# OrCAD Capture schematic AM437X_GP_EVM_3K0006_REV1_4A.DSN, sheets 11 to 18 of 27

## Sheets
11 Pg24: Keypad/LED's: size C
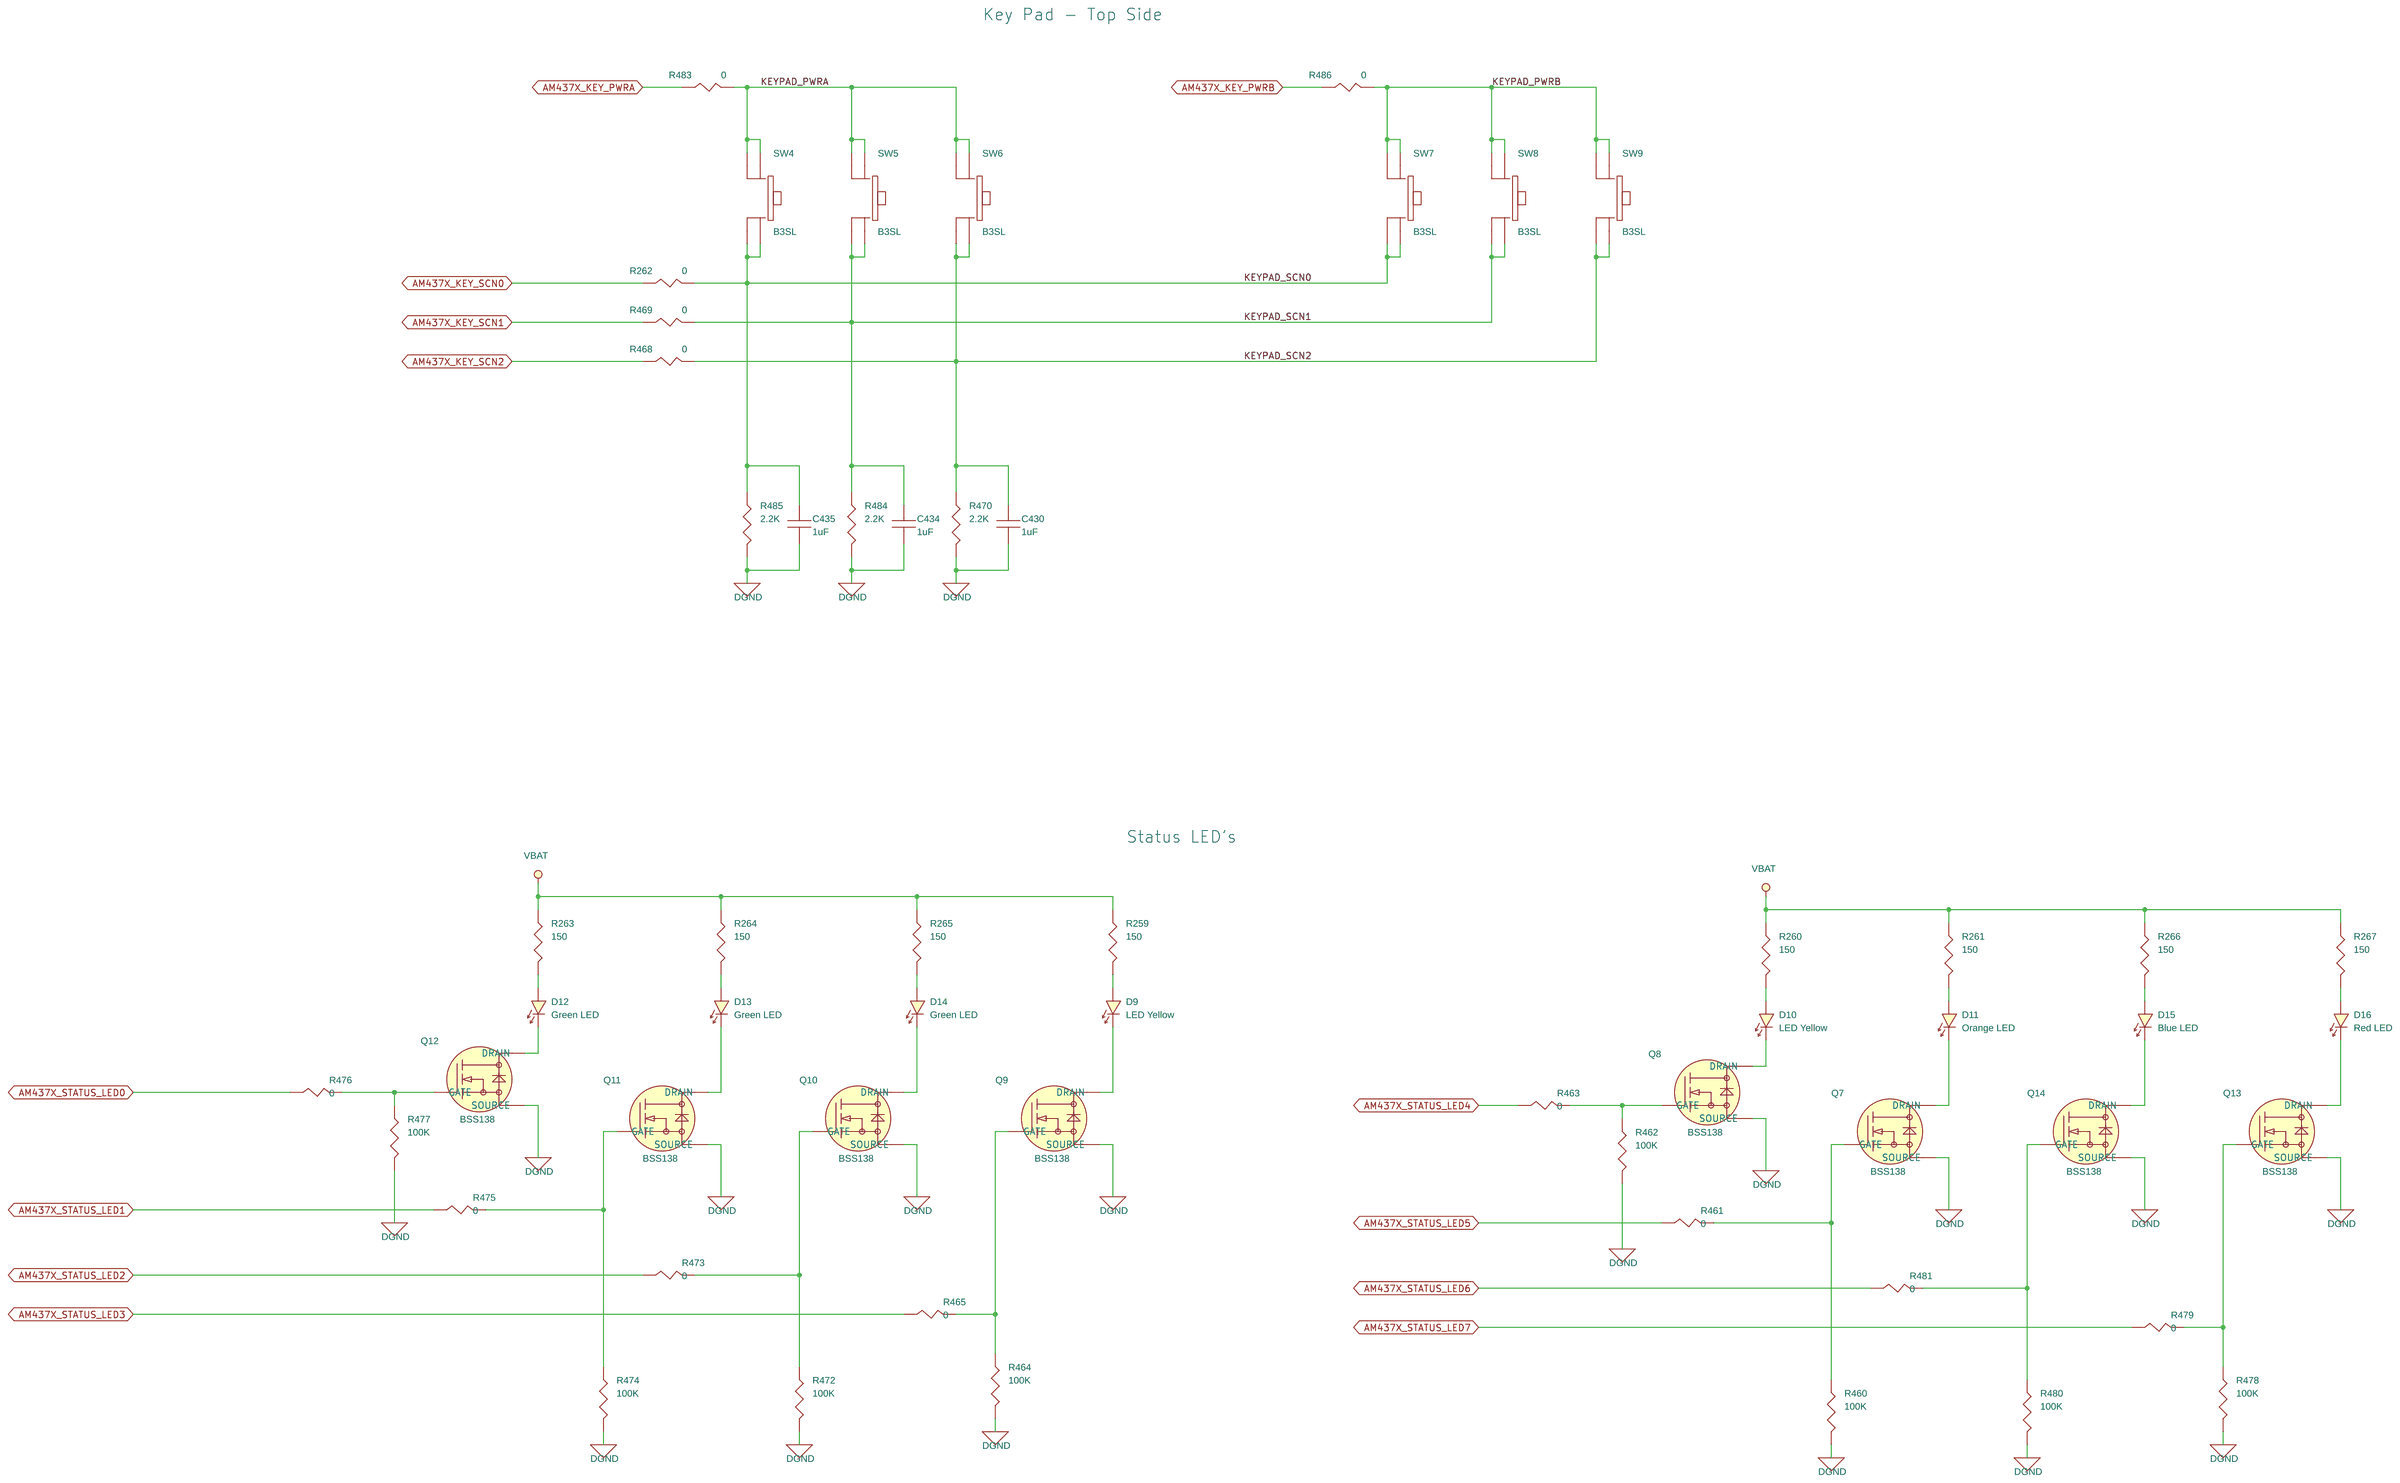
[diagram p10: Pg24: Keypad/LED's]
12 Pg06: DDR3 Memory: size C
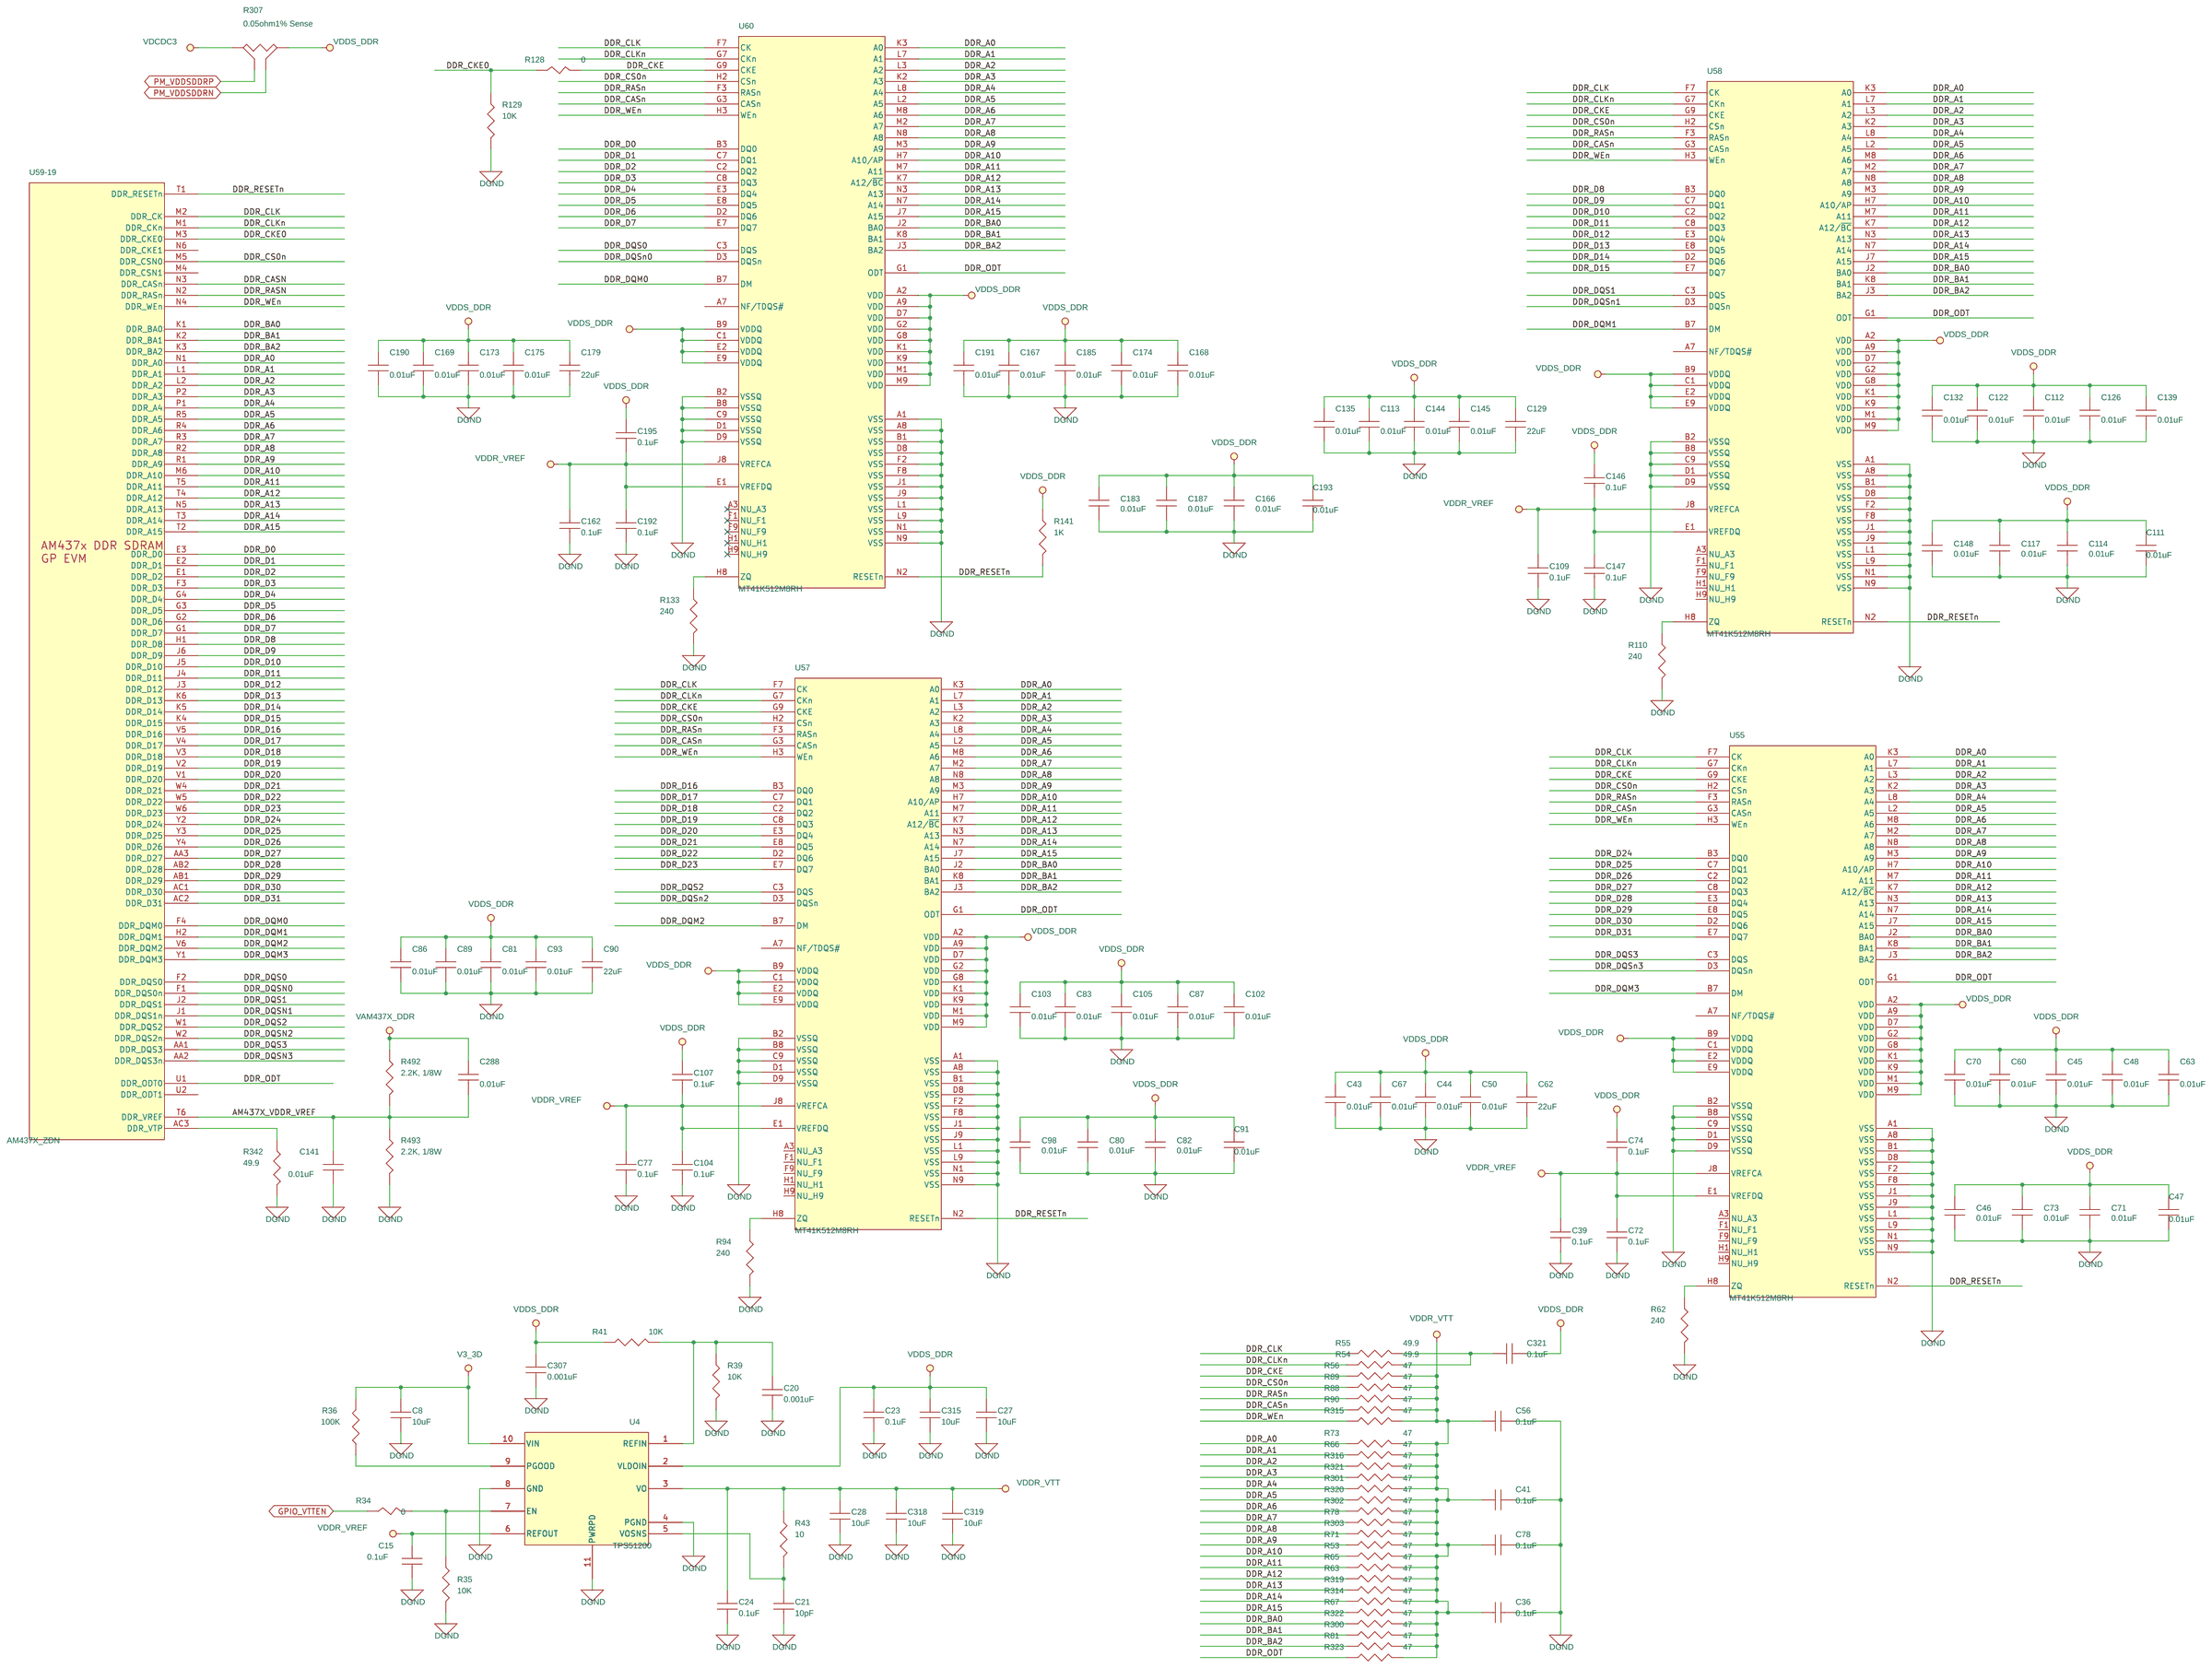
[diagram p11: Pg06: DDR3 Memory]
13 Pg01: Title Page
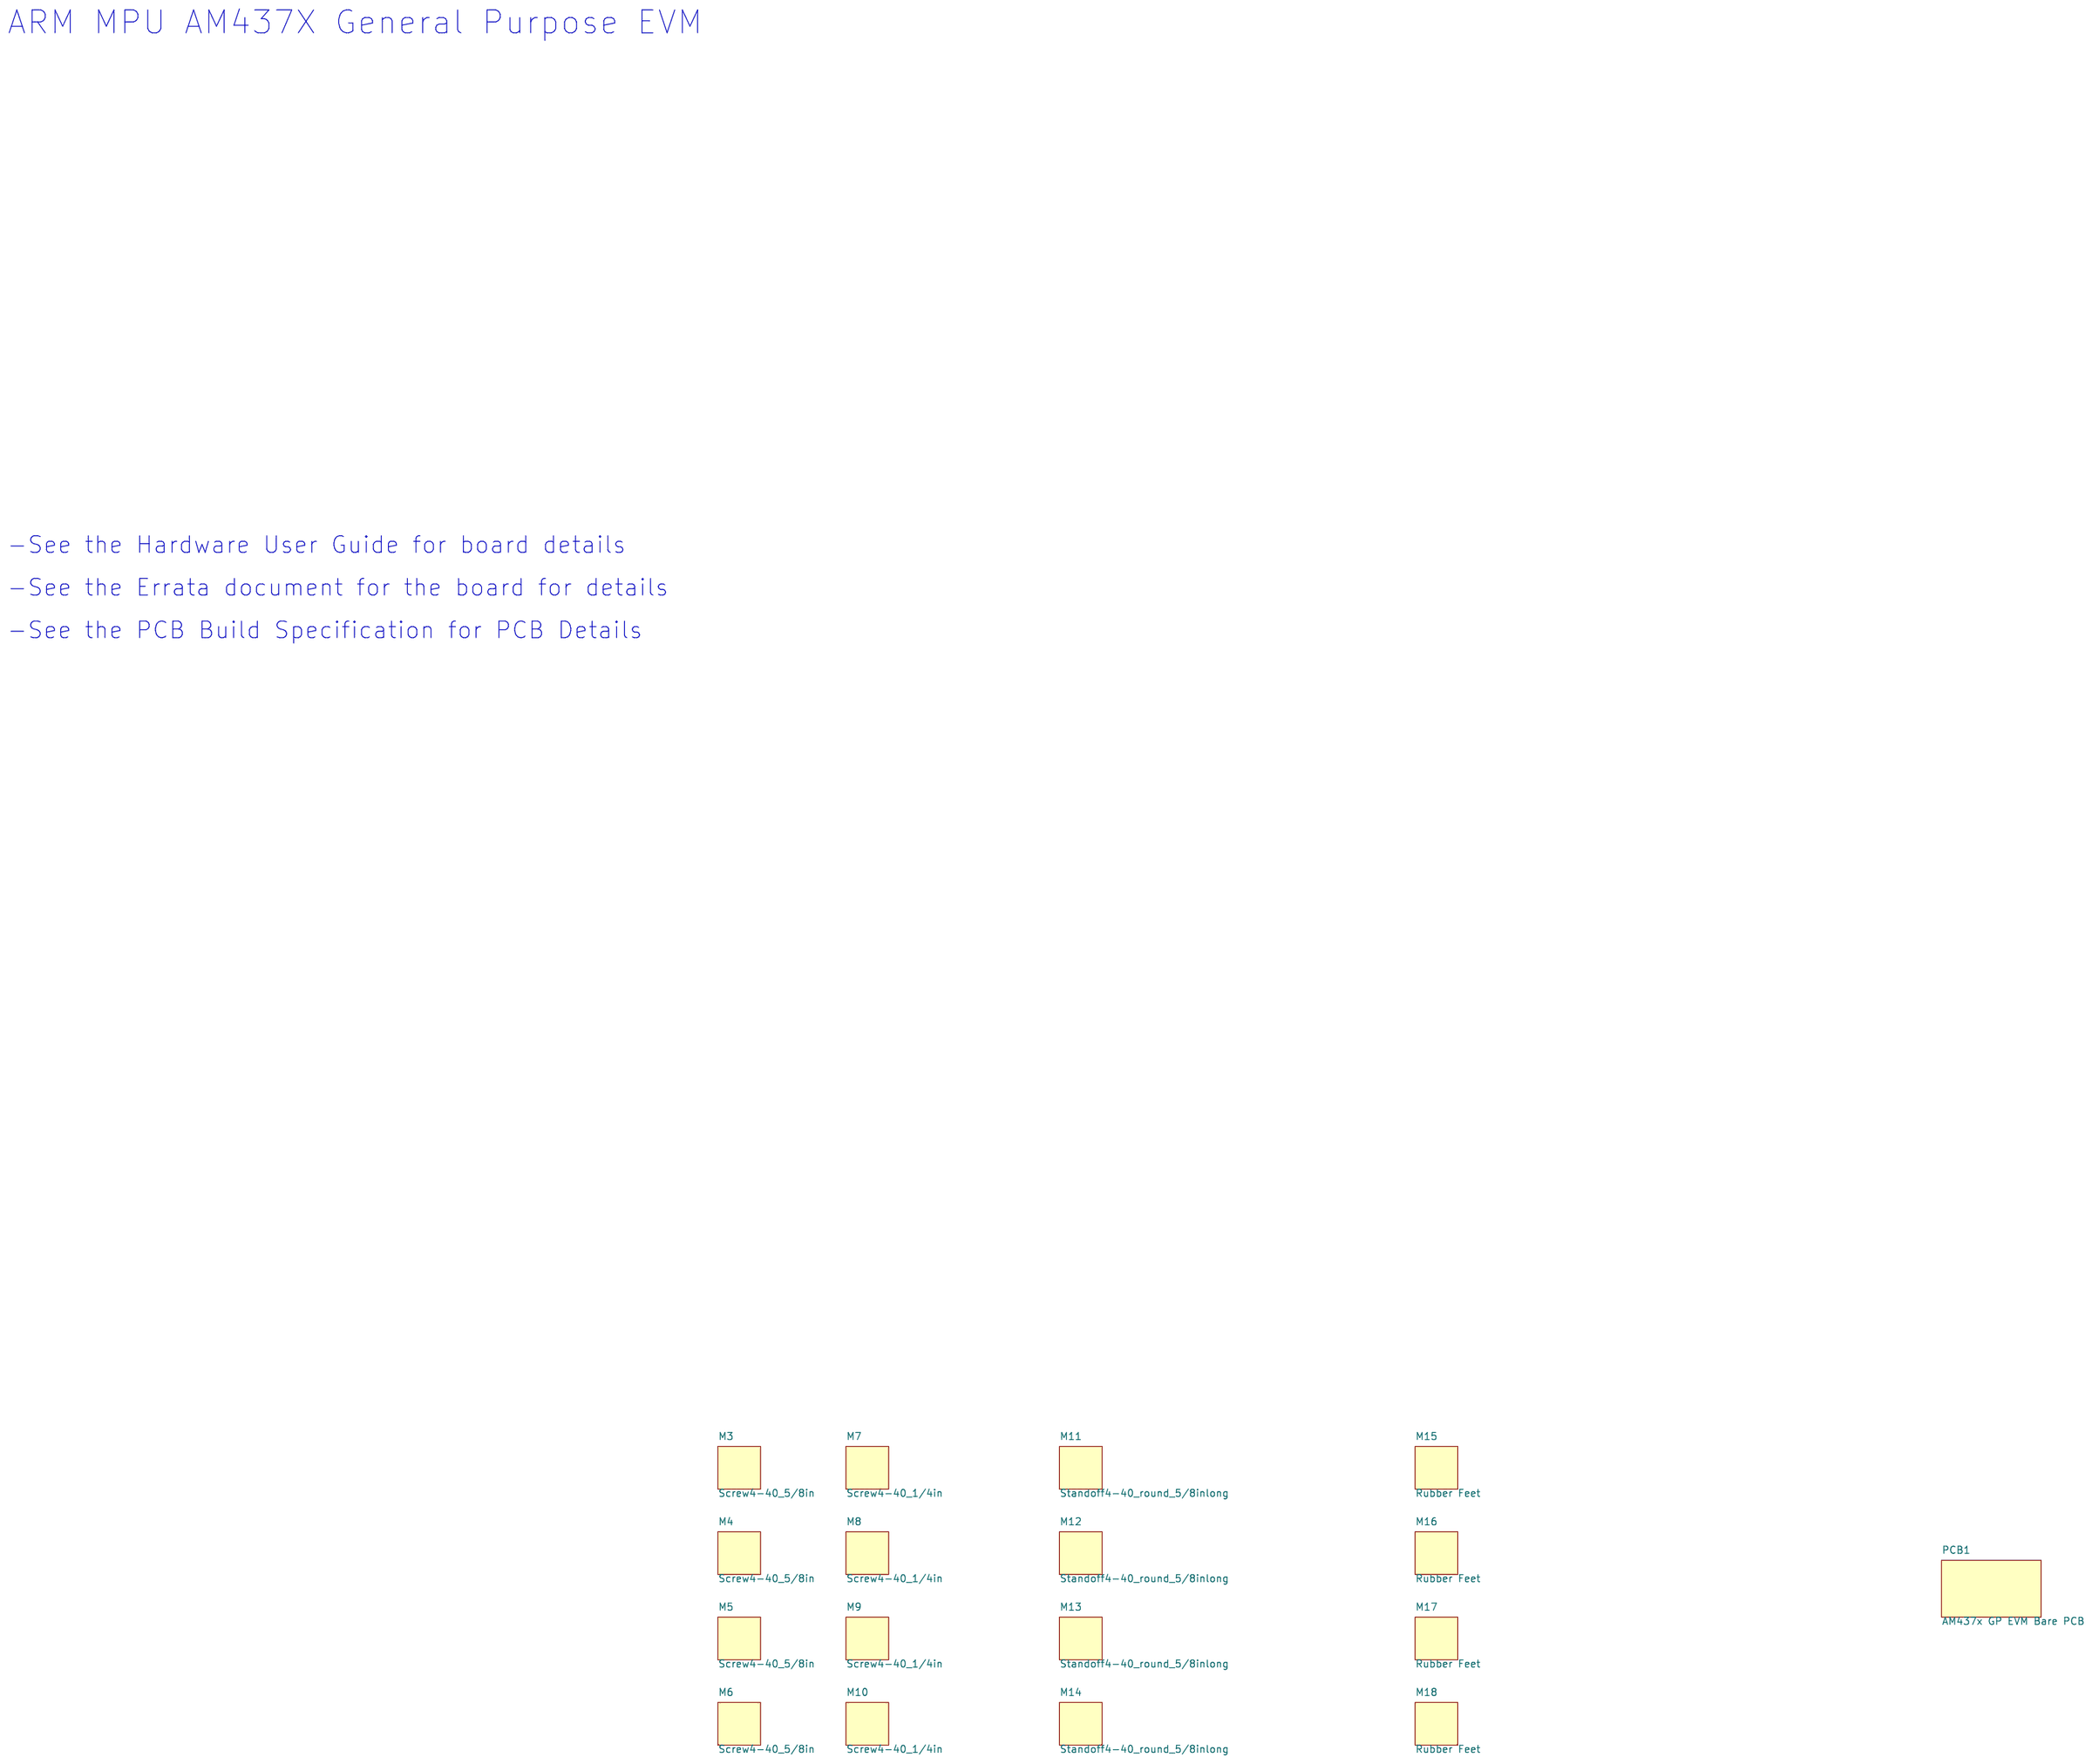
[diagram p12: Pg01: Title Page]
14 Pg25: JTAG Debug: size C
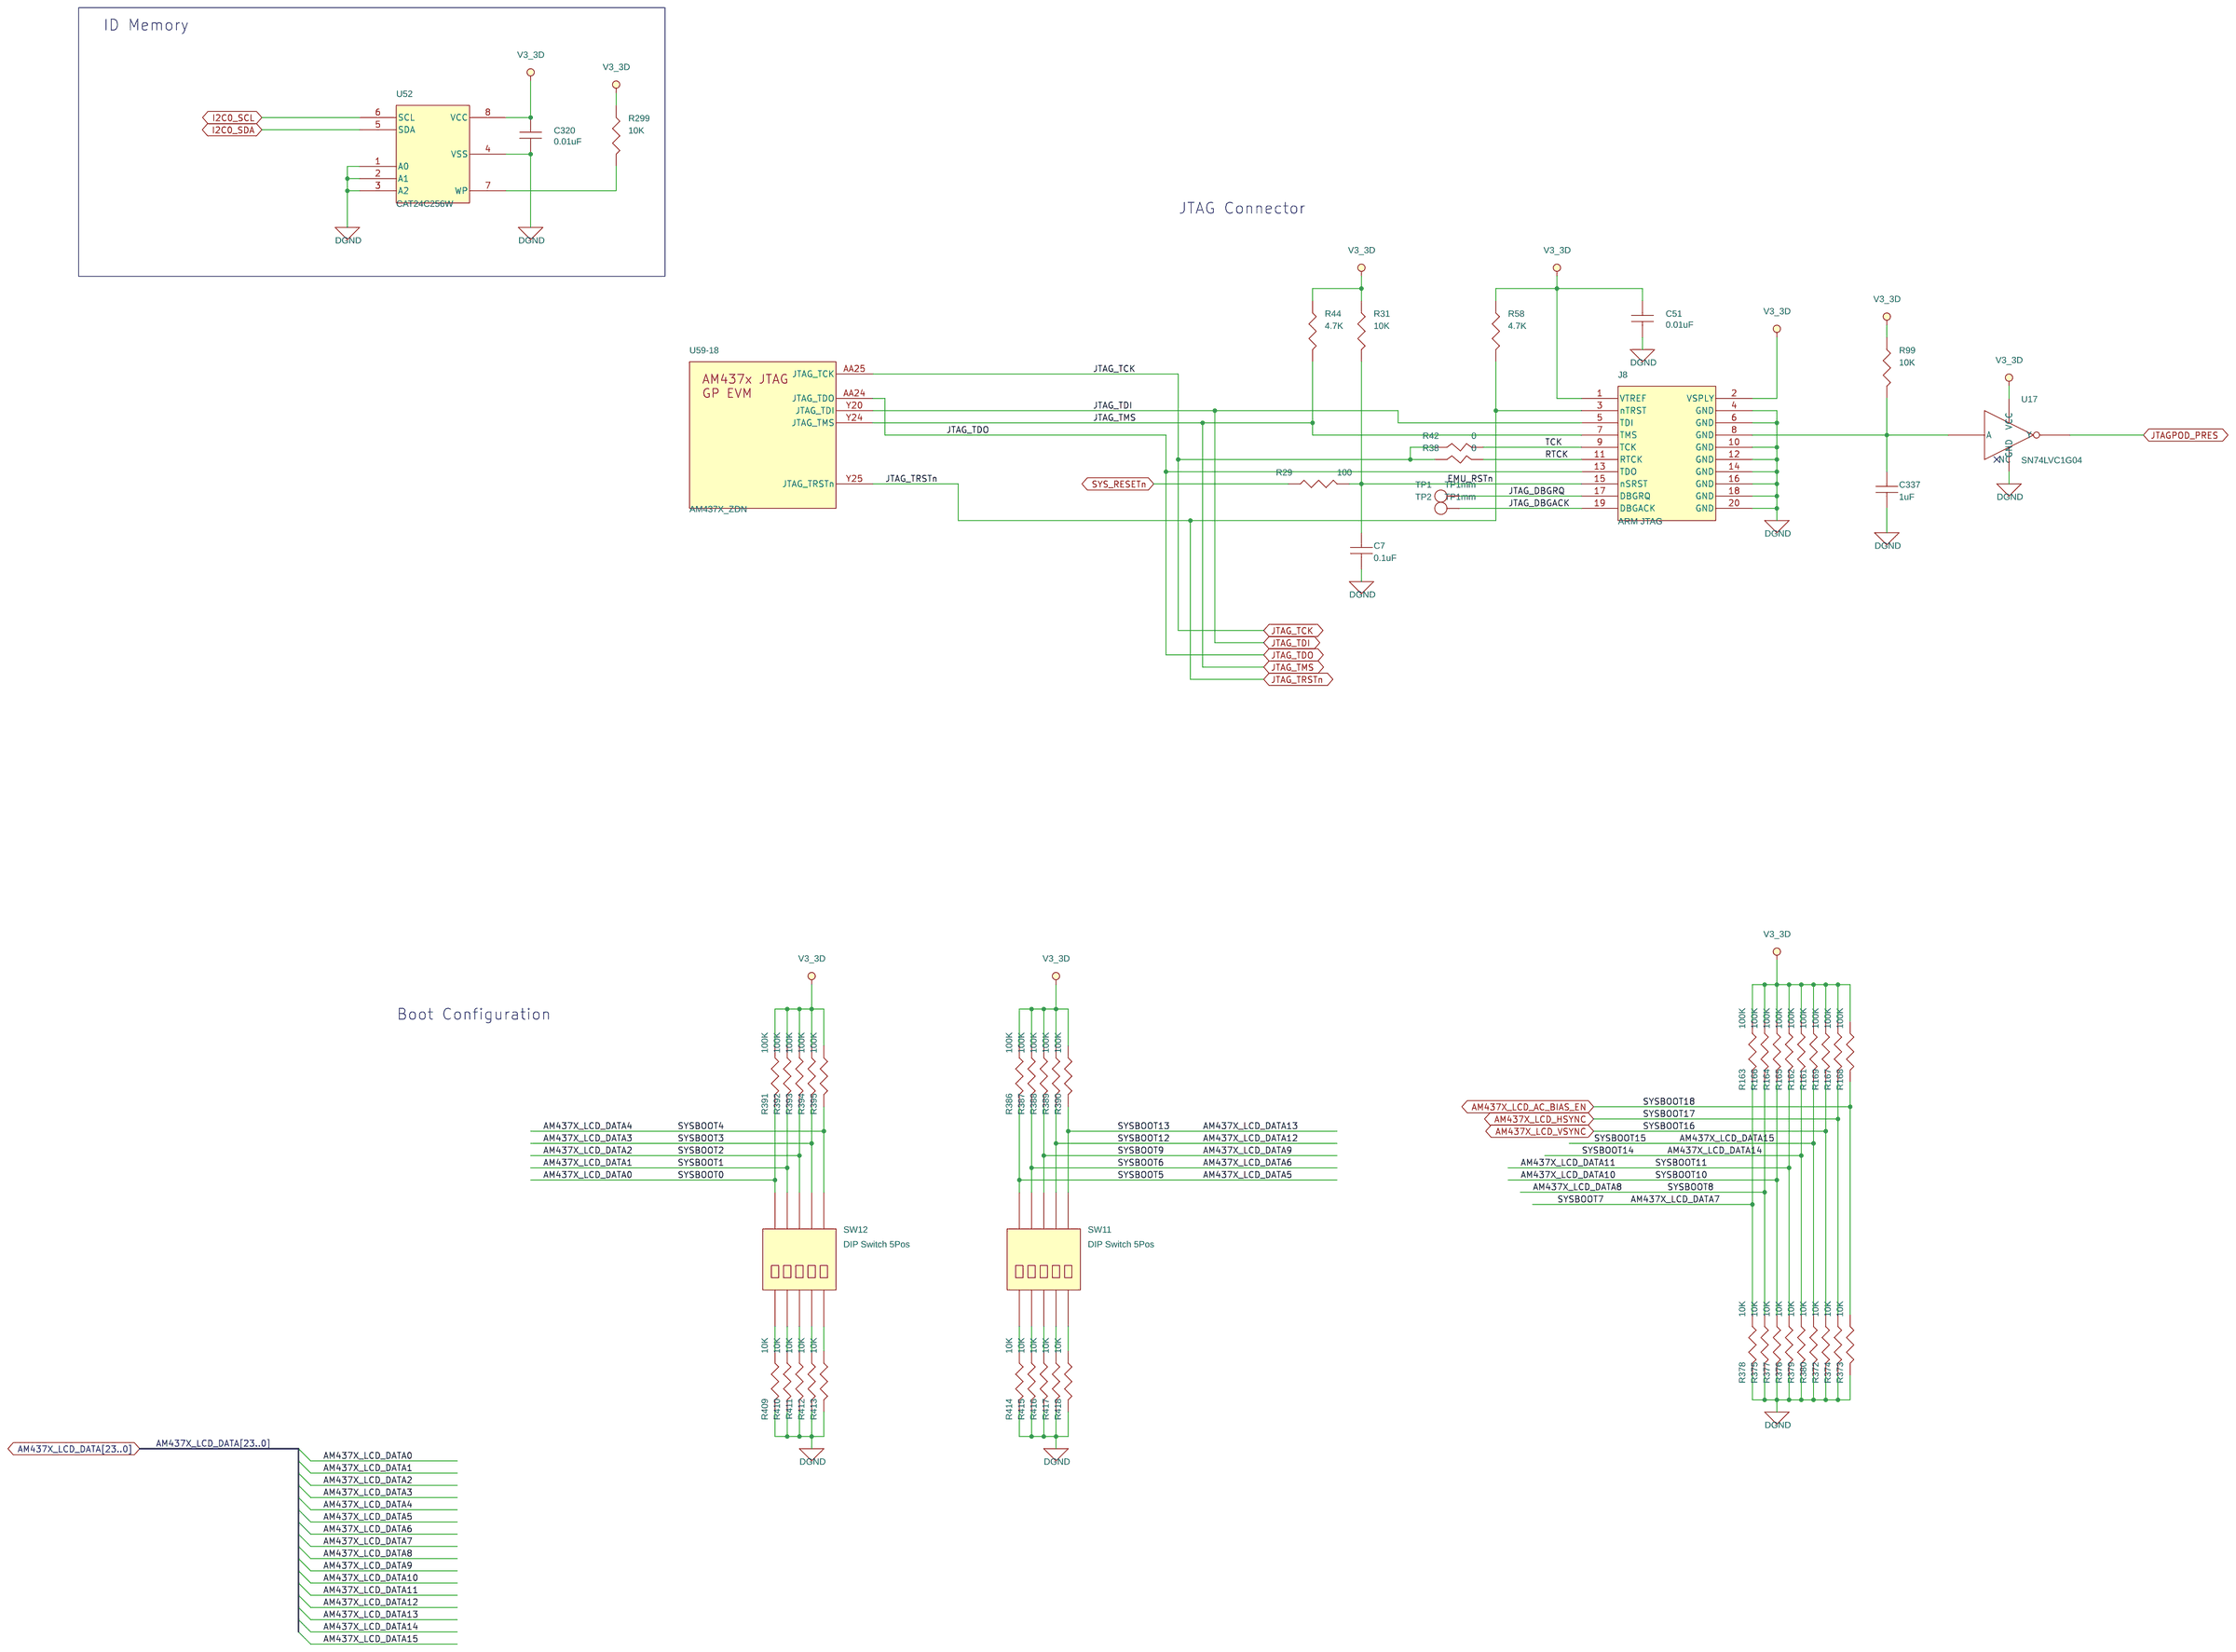
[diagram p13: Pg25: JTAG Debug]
15 Pg07: Ethernet #1: size C
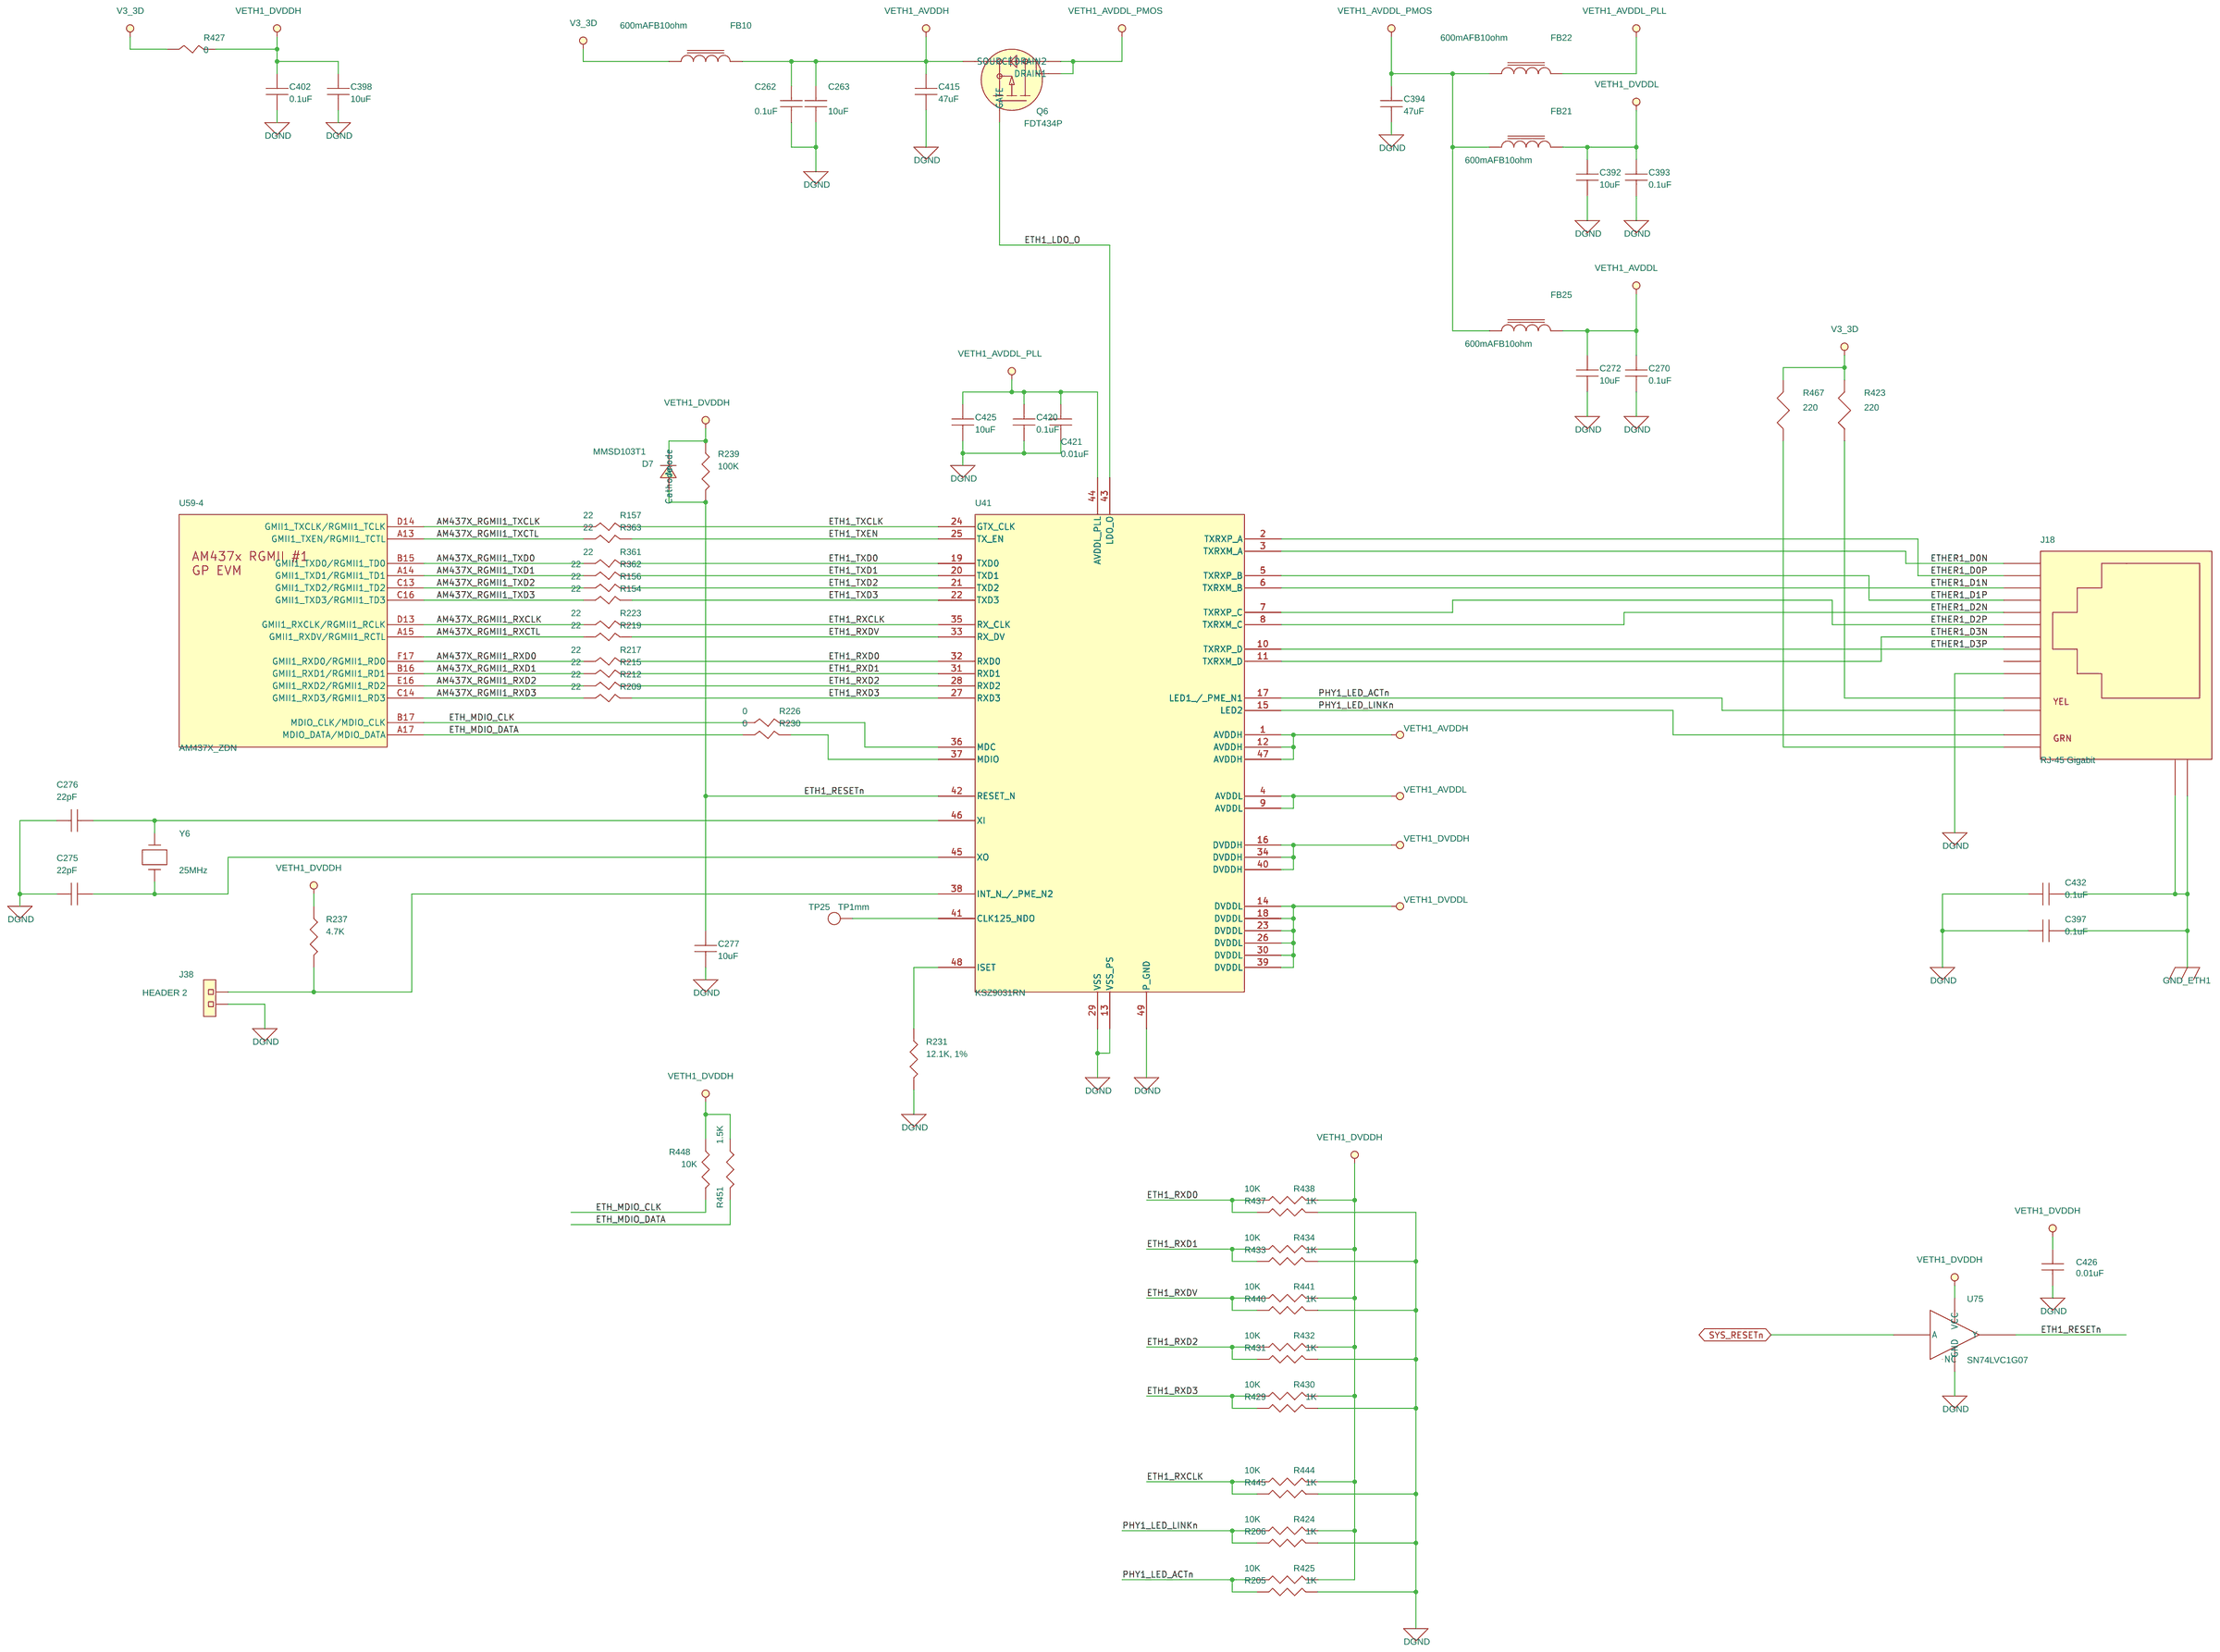
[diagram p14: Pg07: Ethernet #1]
16 Pg17: USB Port #0: size C
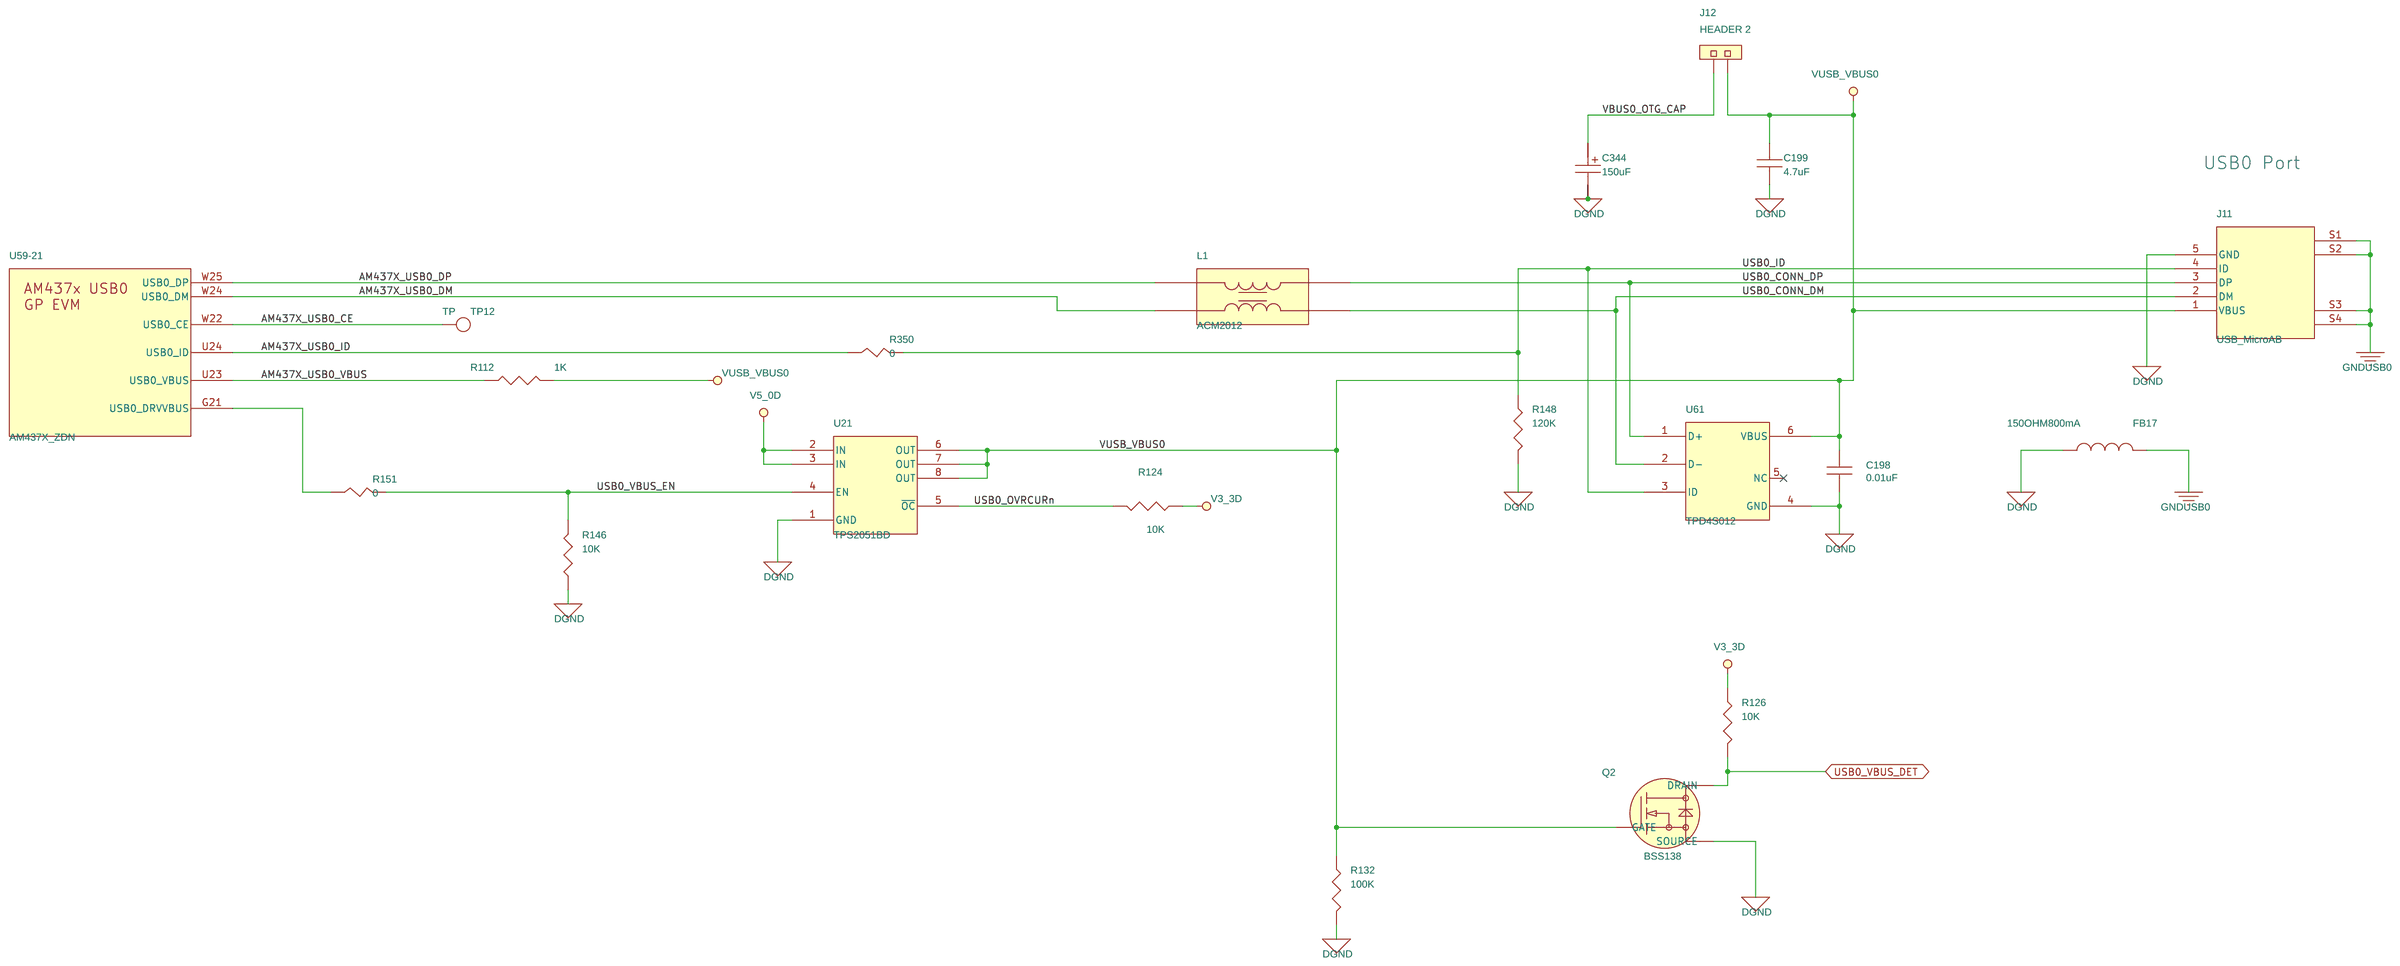
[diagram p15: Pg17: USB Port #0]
17 Pg18: USB Port #1: size C
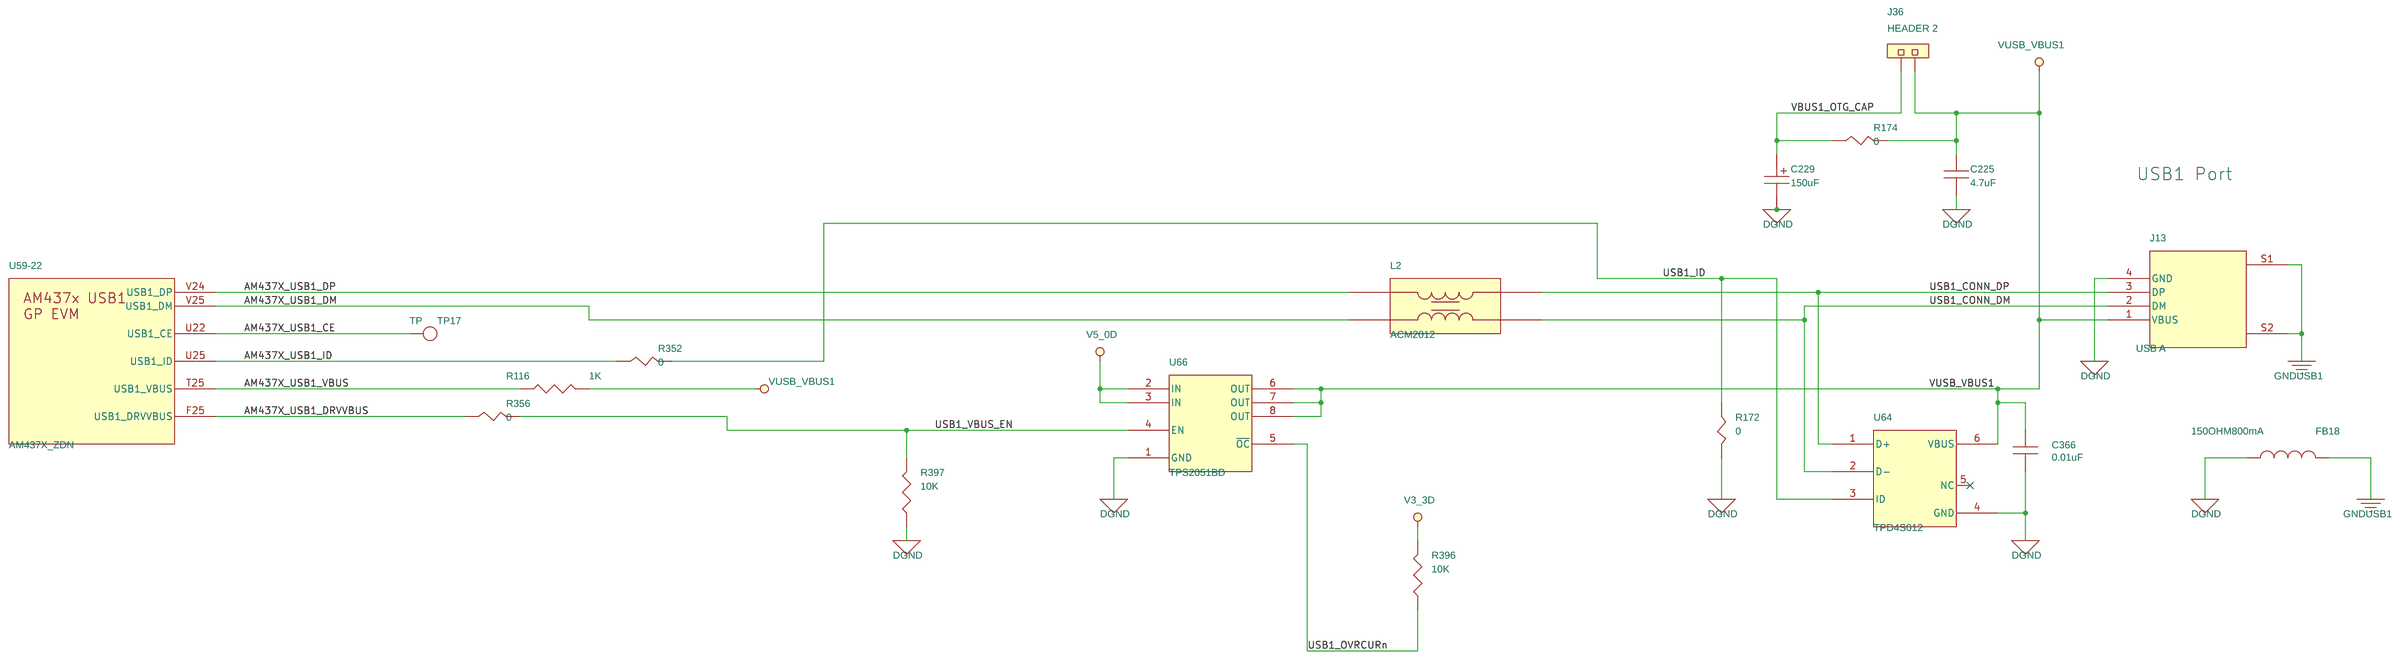
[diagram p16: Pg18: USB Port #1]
18 Pg03: Processor Power: size C
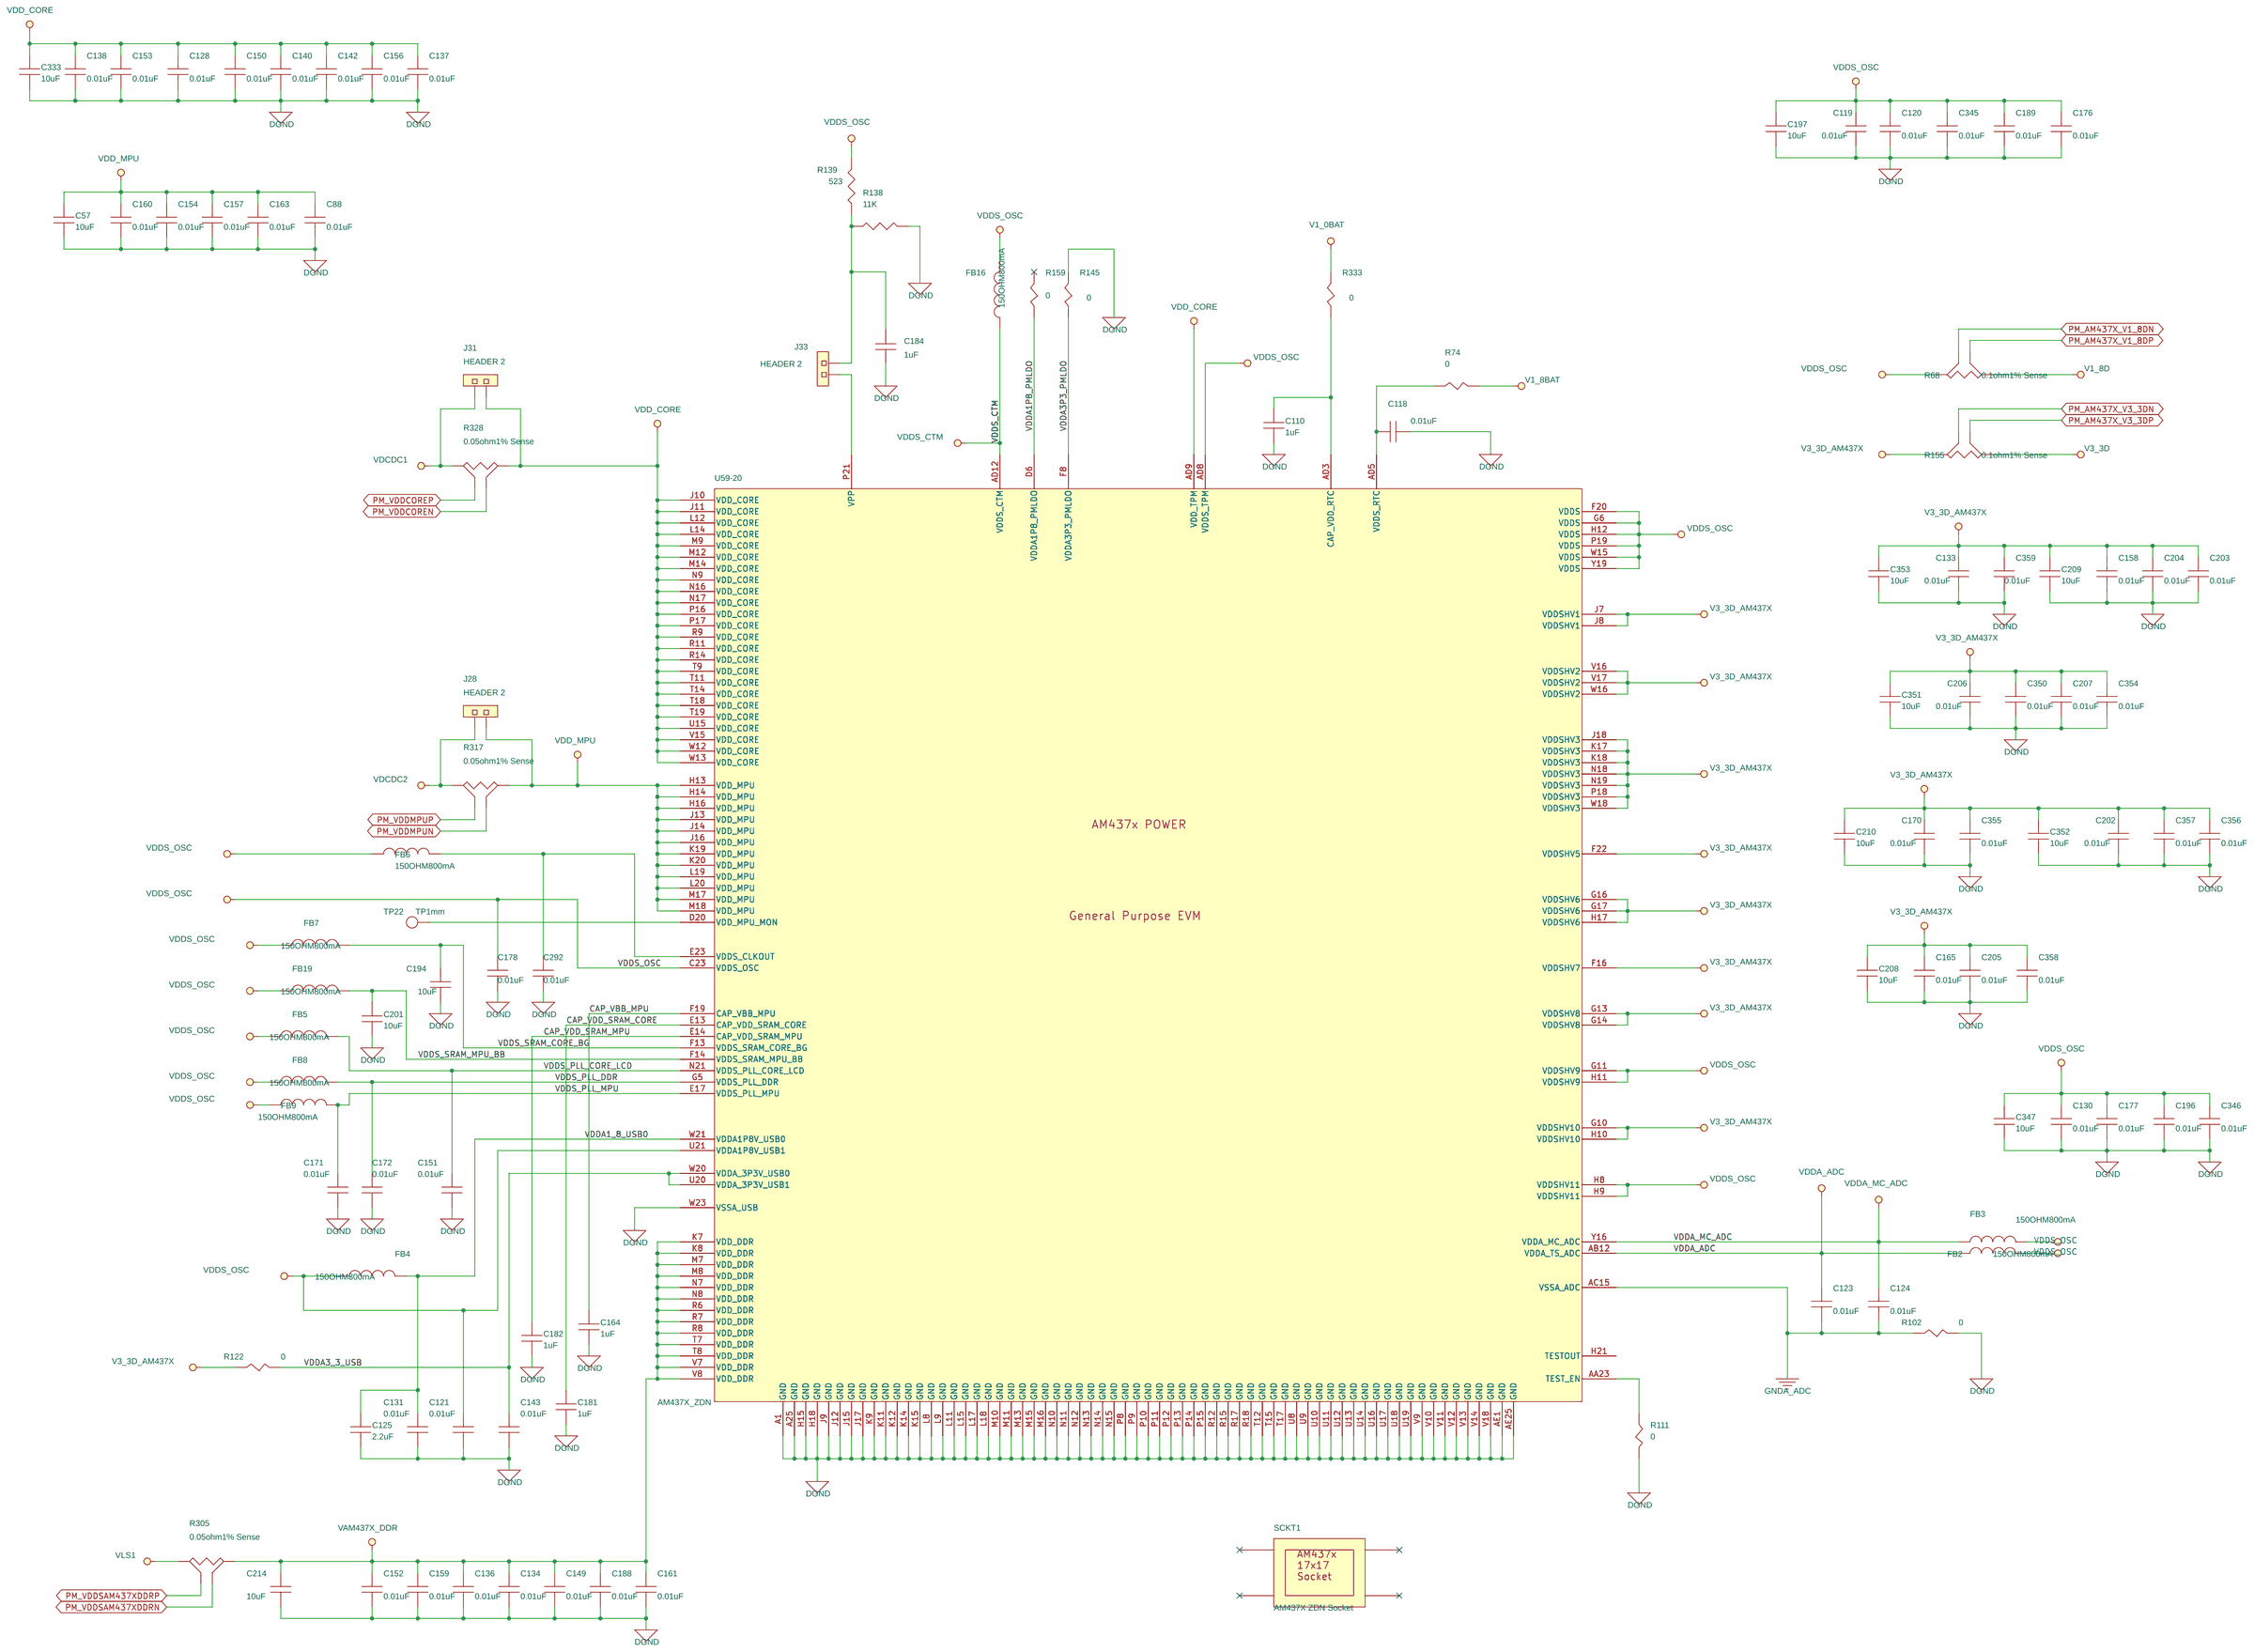
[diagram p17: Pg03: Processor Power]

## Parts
sheet Pg01: Title Page
M3  Screw4-40_5/8in  [DNP]
M4  Screw4-40_5/8in  [DNP]
M5  Screw4-40_5/8in  [DNP]
M6  Screw4-40_5/8in  [DNP]
M7  Screw4-40_1/4in  [DNP]
M8  Screw4-40_1/4in  [DNP]
M9  Screw4-40_1/4in  [DNP]
M10  Screw4-40_1/4in  [DNP]
M11  Standoff4-40_round_5/8inlong  [DNP]
M12  Standoff4-40_round_5/8inlong  [DNP]
M13  Standoff4-40_round_5/8inlong  [DNP]
M14  Standoff4-40_round_5/8inlong  [DNP]
M15  Rubber Feet  [DNP]
M16  Rubber Feet  [DNP]
M17  Rubber Feet  [DNP]
M18  Rubber Feet  [DNP]
PCB1  AM437x GP EVM Bare PCB  [DNP]
sheet Pg03: Processor Power
C57  10uF  [SM-7351-CAP-0805]
C88  0.01uF  [SM-7351-CAP-0402]
C110  1uF  [SM-7351-CAP-0402]
C118  0.01uF  [SM-7351-CAP-0402]
C119  0.01uF  [SM-7351-CAP-0402]
C120  0.01uF  [SM-7351-CAP-0402]
C121  0.01uF  [SM-7351-CAP-0402]
C123  0.01uF  [SM-7351-CAP-0402]
C124  0.01uF  [SM-7351-CAP-0402]
C125  2.2uF  [SM-7351-CAP-0805]
C128  0.01uF  [SM-7351-CAP-0402]
C130  0.01uF  [SM-7351-CAP-0402]
C131  0.01uF  [SM-7351-CAP-0402]
C133  0.01uF  [SM-7351-CAP-0402]
C134  0.01uF  [SM-7351-CAP-0402]
C136  0.01uF  [SM-7351-CAP-0402]
C137  0.01uF  [SM-7351-CAP-0402]
C138  0.01uF  [SM-7351-CAP-0402]
C140  0.01uF  [SM-7351-CAP-0402]
C142  0.01uF  [SM-7351-CAP-0402]
C143  0.01uF  [SM-7351-CAP-0402]
C149  0.01uF  [SM-7351-CAP-0402]
C150  0.01uF  [SM-7351-CAP-0402]
C151  0.01uF  [SM-7351-CAP-0402]
C152  0.01uF  [SM-7351-CAP-0402]
C153  0.01uF  [SM-7351-CAP-0402]
C154  0.01uF  [SM-7351-CAP-0402]
C156  0.01uF  [SM-7351-CAP-0402]
C157  0.01uF  [SM-7351-CAP-0402]
C158  0.01uF  [SM-7351-CAP-0402]
C159  0.01uF  [SM-7351-CAP-0402]
C160  0.01uF  [SM-7351-CAP-0402]
C161  0.01uF  [SM-7351-CAP-0402]
C163  0.01uF  [SM-7351-CAP-0402]
C164  1uF  [SM-7351-CAP-0402]
C165  0.01uF  [SM-7351-CAP-0402]
C170  0.01uF  [SM-7351-CAP-0402]
C171  0.01uF  [SM-7351-CAP-0402]
C172  0.01uF  [SM-7351-CAP-0402]
C176  0.01uF  [SM-7351-CAP-0402]
C177  0.01uF  [SM-7351-CAP-0402]
C178  0.01uF  [SM-7351-CAP-0402]
C181  1uF  [SM-7351-CAP-0402]
C182  1uF  [SM-7351-CAP-0402]
C184  1uF  [SM-7351-CAP-0402]
C188  0.01uF  [SM-7351-CAP-0402]
C189  0.01uF  [SM-7351-CAP-0402]
C194  10uF  [SM-7351-CAP-0603]
C196  0.01uF  [SM-7351-CAP-0402]
C197  10uF  [SM-7351-CAP-0805]
C201  10uF  [SM-7351-CAP-0603]
C202  0.01uF  [SM-7351-CAP-0402]
C203  0.01uF  [SM-7351-CAP-0402]
C204  0.01uF  [SM-7351-CAP-0402]
C205  0.01uF  [SM-7351-CAP-0402]
C206  0.01uF  [SM-7351-CAP-0402]
C207  0.01uF  [SM-7351-CAP-0402]
C208  10uF  [SM-7351-CAP-0805]
C209  10uF  [SM-7351-CAP-0805]
C210  10uF  [SM-7351-CAP-0805]
C214  10uF  [SM-7351-CAP-0805]
C292  0.01uF  [SM-7351-CAP-0402]
C333  10uF  [SM-7351-CAP-0805]
C345  0.01uF  [SM-7351-CAP-0402]
C346  0.01uF  [SM-7351-CAP-0402]
C347  10uF  [SM-7351-CAP-0805]
C350  0.01uF  [SM-7351-CAP-0402]
C351  10uF  [SM-7351-CAP-0805]
C352  10uF  [SM-7351-CAP-0805]
C353  10uF  [SM-7351-CAP-0805]
C354  0.01uF  [SM-7351-CAP-0402]
C355  0.01uF  [SM-7351-CAP-0402]
C356  0.01uF  [SM-7351-CAP-0402]
C357  0.01uF  [SM-7351-CAP-0402]
C358  0.01uF  [SM-7351-CAP-0402]
C359  0.01uF  [SM-7351-CAP-0402]
FB2  150OHM800mA  [sm-7351-ind-0805]
FB3  150OHM800mA  [sm-7351-ind-0805]
FB4  150OHM800mA  [sm-7351-ind-0805]
FB5  150OHM800mA  [sm-7351-ind-0805]
FB6  150OHM800mA  [sm-7351-ind-0805]
FB7  150OHM800mA  [sm-7351-ind-0805]
FB8  150OHM800mA  [sm-7351-ind-0805]
FB9  150OHM800mA  [sm-7351-ind-0805]
FB16  150OHM800mA  [sm-7351-ind-0805]
FB19  150OHM800mA  [sm-7351-ind-0805]
J28  HEADER 2  [header_2x1]
J31  HEADER 2  [header_2x1]
J33  HEADER 2  [header_2x1]
R68  0.1ohm1% Sense  [SM_RES_0805_KELV]
R74  0  [SM-7351-RES-0402]
R102  0  [SM-7351-RES-0402]
R111  0  [SM-7351-RES-0402]
R122  0  [SM-7351-RES-0402]
R138  11K  [SM-7351-RES-0402]
R139  523  [SM-7351-RES-0402]
R145  0  [SM-7351-RES-0603]
R155  0.1ohm1% Sense  [SM_RES_0805_KELV]
R159  0  [SM-7351-RES-0603]
R305  0.05ohm1% Sense  [SM_RES_LVK12]
R317  0.05ohm1% Sense  [SM_RES_LVK12]
R328  0.05ohm1% Sense  [SM_RES_LVK12]
R333  0  [SM-7351-RES-0603]
SCKT1  AM437X ZDN Socket  [SCKBGA625]
TP22  TP1mm  [tp_smd1mmcircle]
sheet Pg06: DDR3 Memory
C8  10uF  [SM-7351-CAP-0805]
C15  0.1uF  [SM-7351-CAP-0402]
C20  0.001uF  [SM-7351-CAP-0402]
C21  10pF  [SM-7351-CAP-0402]
C23  0.1uF  [SM-7351-CAP-0402]
C24  0.1uF  [SM-7351-CAP-0402]
C27  10uF  [SM-7351-CAP-0805]
C28  10uF  [SM-7351-CAP-0805]
C36  0.1uF  [SM-7351-CAP-0402]
C39  0.1uF  [SM-7351-CAP-0402]
C41  0.1uF  [SM-7351-CAP-0402]
C43  0.01uF  [SM-7351-CAP-0402]
C44  0.01uF  [SM-7351-CAP-0402]
C45  0.01uF  [SM-7351-CAP-0402]
C46  0.01uF  [SM-7351-CAP-0402]
C47  0.01uF  [SM-7351-CAP-0402]
C48  0.01uF  [SM-7351-CAP-0402]
C50  0.01uF  [SM-7351-CAP-0402]
C56  0.1uF  [SM-7351-CAP-0402]
C60  0.01uF  [SM-7351-CAP-0402]
C62  22uF  [SM-7351-CAP-0805]
C63  0.01uF  [SM-7351-CAP-0402]
C67  0.01uF  [SM-7351-CAP-0402]
C70  0.01uF  [SM-7351-CAP-0402]
C71  0.01uF  [SM-7351-CAP-0402]
C72  0.1uF  [SM-7351-CAP-0402]
C73  0.01uF  [SM-7351-CAP-0402]
C74  0.1uF  [SM-7351-CAP-0402]
C77  0.1uF  [SM-7351-CAP-0402]
C78  0.1uF  [SM-7351-CAP-0402]
C80  0.01uF  [SM-7351-CAP-0402]
C81  0.01uF  [SM-7351-CAP-0402]
C82  0.01uF  [SM-7351-CAP-0402]
C83  0.01uF  [SM-7351-CAP-0402]
C86  0.01uF  [SM-7351-CAP-0402]
C87  0.01uF  [SM-7351-CAP-0402]
C89  0.01uF  [SM-7351-CAP-0402]
C90  22uF  [SM-7351-CAP-0805]
C91  0.01uF  [SM-7351-CAP-0402]
C93  0.01uF  [SM-7351-CAP-0402]
C98  0.01uF  [SM-7351-CAP-0402]
C102  0.01uF  [SM-7351-CAP-0402]
C103  0.01uF  [SM-7351-CAP-0402]
C104  0.1uF  [SM-7351-CAP-0402]
C105  0.01uF  [SM-7351-CAP-0402]
C107  0.1uF  [SM-7351-CAP-0402]
C109  0.1uF  [SM-7351-CAP-0402]
C111  0.01uF  [SM-7351-CAP-0402]
C112  0.01uF  [SM-7351-CAP-0402]
C113  0.01uF  [SM-7351-CAP-0402]
C114  0.01uF  [SM-7351-CAP-0402]
C117  0.01uF  [SM-7351-CAP-0402]
C122  0.01uF  [SM-7351-CAP-0402]
C126  0.01uF  [SM-7351-CAP-0402]
C129  22uF  [SM-7351-CAP-0805]
C132  0.01uF  [SM-7351-CAP-0402]
C135  0.01uF  [SM-7351-CAP-0402]
C139  0.01uF  [SM-7351-CAP-0402]
C141  0.01uF  [SM-7351-CAP-0402]
C144  0.01uF  [SM-7351-CAP-0402]
C145  0.01uF  [SM-7351-CAP-0402]
C146  0.1uF  [SM-7351-CAP-0402]
C147  0.1uF  [SM-7351-CAP-0402]
C148  0.01uF  [SM-7351-CAP-0402]
C162  0.1uF  [SM-7351-CAP-0402]
C166  0.01uF  [SM-7351-CAP-0402]
C167  0.01uF  [SM-7351-CAP-0402]
C168  0.01uF  [SM-7351-CAP-0402]
C169  0.01uF  [SM-7351-CAP-0402]
C173  0.01uF  [SM-7351-CAP-0402]
C174  0.01uF  [SM-7351-CAP-0402]
C175  0.01uF  [SM-7351-CAP-0402]
C179  22uF  [SM-7351-CAP-0805]
C183  0.01uF  [SM-7351-CAP-0402]
C185  0.01uF  [SM-7351-CAP-0402]
C187  0.01uF  [SM-7351-CAP-0402]
C190  0.01uF  [SM-7351-CAP-0402]
C191  0.01uF  [SM-7351-CAP-0402]
C192  0.1uF  [SM-7351-CAP-0402]
C193  0.01uF  [SM-7351-CAP-0402]
C195  0.1uF  [SM-7351-CAP-0402]
C288  0.01uF  [SM-7351-CAP-0402]
C307  0.001uF  [SM-7351-CAP-0402]
C315  10uF  [SM-7351-CAP-0805]
C318  10uF  [SM-7351-CAP-0805]
C319  10uF  [SM-7351-CAP-0805]
C321  0.1uF  [SM-7351-CAP-0402]
R34  0  [SM-7351-RES-0402]
R35  10K  [SM-7351-RES-0402]
R36  100K  [SM-7351-RES-0402]
R39  10K  [SM-7351-RES-0402]
R41  10K  [SM-7351-RES-0402]
R43  10  [SM-7351-RES-0402]
R53  47  [SM-7351-RES-0402]
R54  49.9  [SM-7351-RES-0402]
R55  49.9  [SM-7351-RES-0402]
R56  47  [SM-7351-RES-0402]
R62  240  [sm-7351-res-0402]
R63  47  [SM-7351-RES-0402]
R65  47  [SM-7351-RES-0402]
R66  47  [SM-7351-RES-0402]
R67  47  [SM-7351-RES-0402]
R71  47  [SM-7351-RES-0402]
R73  47  [SM-7351-RES-0402]
R78  47  [SM-7351-RES-0402]
R81  47  [SM-7351-RES-0402]
R88  47  [SM-7351-RES-0402]
R89  47  [SM-7351-RES-0402]
R90  47  [SM-7351-RES-0402]
R94  240  [sm-7351-res-0402]
R110  240  [sm-7351-res-0402]
R128  0  [SM-7351-RES-0402]
R129  10K  [SM-7351-RES-0402]
R133  240  [sm-7351-res-0402]
R141  1K  [SM-7351-RES-0402]
R300  47  [SM-7351-RES-0402]
R301  47  [SM-7351-RES-0402]
R302  47  [SM-7351-RES-0402]
R303  47  [SM-7351-RES-0402]
R307  0.05ohm1% Sense  [SM_RES_LVK12]
R314  47  [SM-7351-RES-0402]
R315  47  [SM-7351-RES-0402]
R316  47  [SM-7351-RES-0402]
R319  47  [SM-7351-RES-0402]
R320  47  [SM-7351-RES-0402]
R321  47  [SM-7351-RES-0402]
R322  47  [SM-7351-RES-0402]
R323  47  [SM-7351-RES-0402]
R342  49.9  [SM-7351-RES-0402]
R492  2.2K, 1/8W  [SM-7351-RES-0402]
R493  2.2K, 1/8W  [SM-7351-RES-0402]
U4  TPS51200  [drcpso_10pin]
U55  MT41K512M8RH  [bga11x9-78]
U57  MT41K512M8RH  [bga11x9-78]
U58  MT41K512M8RH  [bga11x9-78]
U60  MT41K512M8RH  [bga11x9-78]
sheet Pg07: Ethernet #1
C262  0.1uF  [SM-7351-CAP-0402]
C263  10uF  [SM-7351-CAP-0805]
C270  0.1uF  [SM-7351-CAP-0402]
C272  10uF  [SM-7351-CAP-0805]
C275  22pF  [SM-7351-CAP-0402]
C276  22pF  [SM-7351-CAP-0402]
C277  10uF  [SM-7351-CAP-0805]
C392  10uF  [SM-7351-CAP-0805]
C393  0.1uF  [SM-7351-CAP-0402]
C394  47uF  [SM-7351-CAP-1206]
C397  0.1uF  [SM-7351-CAP-0402]
C398  10uF  [SM-7351-CAP-0805]
C402  0.1uF  [SM-7351-CAP-0402]
C415  47uF  [SM-7351-CAP-1206]
C420  0.1uF  [SM-7351-CAP-0402]
C421  0.01uF  [SM-7351-CAP-0402]
C425  10uF  [SM-7351-CAP-0805]
C426  0.01uF  [SM-7351-CAP-0402]
C432  0.1uF  [SM-7351-CAP-0402]
D7  MMSD103T1  [sod-123]
FB10  600mAFB10ohm  [HF70ACB201209]
FB21  600mAFB10ohm  [HF70ACB201209]
FB22  600mAFB10ohm  [HF70ACB201209]
FB25  600mAFB10ohm  [HF70ACB201209]
J18  RJ-45 Gigabit  [cnrj45-1x1wled-598m]
J38  HEADER 2  [header_2x1]
Q6  FDT434P  [SOT223-4]
R154  22  [SM-7351-RES-0402]
R156  22  [SM-7351-RES-0402]
R157  22  [SM-7351-RES-0402]
R205  1K  [SM-7351-RES-0402]
R206  1K  [SM-7351-RES-0402]
R209  22  [SM-7351-RES-0402]
R212  22  [SM-7351-RES-0402]
R215  22  [SM-7351-RES-0402]
R217  22  [SM-7351-RES-0402]
R219  22  [SM-7351-RES-0402]
R223  22  [SM-7351-RES-0402]
R226  0  [SM-7351-RES-0402]
R230  0  [SM-7351-RES-0402]
R231  12.1K, 1%  [SM-7351-RES-0402]
R237  4.7K  [SM-7351-RES-0402]
R239  100K  [SM-7351-RES-0402]
R361  22  [SM-7351-RES-0402]
R362  22  [SM-7351-RES-0402]
R363  22  [SM-7351-RES-0402]
R423  220  [SM-7351-RES-0402]
R424  10K  [SM-7351-RES-0402]
R425  10K  [SM-7351-RES-0402]
R427  0  [SM-7351-RES-0603]
R429  1K  [SM-7351-RES-0402]
R430  10K  [SM-7351-RES-0402]
R431  1K  [SM-7351-RES-0402]
R432  10K  [SM-7351-RES-0402]
R433  1K  [SM-7351-RES-0402]
R434  10K  [SM-7351-RES-0402]
R437  1K  [SM-7351-RES-0402]
R438  10K  [SM-7351-RES-0402]
R440  1K  [SM-7351-RES-0402]
R441  10K  [SM-7351-RES-0402]
R444  10K  [SM-7351-RES-0402]
R445  1K  [SM-7351-RES-0402]
R448  10K  [SM-7351-RES-0402]
R451  1.5K  [SM-7351-RES-0402]
R467  220  [SM-7351-RES-0402]
TP25  TP1mm  [tp_smd1mmcircle]
U41  KSZ9031RN  [qfn7x7-48]
U75  SN74LVC1G07  [SC70-5-43M]
Y6  25MHz  [SM_OSC_ABM3]
sheet Pg17: USB Port #0
C198  0.01uF  [SM-7351-CAP-0402]
C199  4.7uF  [SM-7351-CAP-0603]
C344  150uF  [SM-7351-CAP-2917]
FB17  150OHM800mA  [sm-7351-ind-0805]
J11  USB_MicroAB  [ZX62-AB-5PA]
J12  HEADER 2  [header_2x1]
L1  ACM2012  [ACM2012H]
Q2  BSS138  [SOT23-3]
R112  1K  [SM-7351-RES-0402]
R124  10K  [SM-7351-RES-0402]
R126  10K  [SM-7351-RES-0402]
R132  100K  [SM-7351-RES-0402]
R146  10K  [SM-7351-RES-0402]
R148  120K  [SM-7351-RES-0402]
R151  0  [SM-7351-RES-0402]
R350  0  [SM-7351-RES-0402]
TP12  TP  [TH_TP_5002]
U21  TPS2051BD  [U_8_D]
U61  TPD4S012  [U_6_DRY]
sheet Pg18: USB Port #1
C225  4.7uF  [SM-7351-CAP-0603]
C229  150uF  [SM-7351-CAP-2917]
C366  0.01uF  [SM-7351-CAP-0402]
FB18  150OHM800mA  [sm-7351-ind-0805]
J13  USB A  [usb_std_a_th]
J36  HEADER 2  [header_2x1]
L2  ACM2012  [ACM2012H]
R116  1K  [SM-7351-RES-0402]
R172  0  [SM-7351-RES-0402]
R174  0  [SM-7351-RES-0603]
R352  0  [SM-7351-RES-0402]
R356  0  [SM-7351-RES-0402]
R396  10K  [SM-7351-RES-0402]
R397  10K  [SM-7351-RES-0402]
TP17  TP  [TH_TP_5002]
U64  TPD4S012  [U_6_DRY]
U66  TPS2051BD  [U_8_D]
sheet Pg23: Unused pins/GPIO
U59  AM437X_ZDN  [AM437X_ZDN]  (sections -1,-10,-11,-12,-13,-14,-15,-16,-17,-18,-19,-2,-20,-21,-22,-23,-24,-25,-3,-4,-5,-6,-7,-8,-9)
sheet Pg24: Keypad/LED's
C430  1uF  [SM-7351-CAP-0402]
C434  1uF  [SM-7351-CAP-0402]
C435  1uF  [SM-7351-CAP-0402]
D9  LED Yellow  [sm_led_0805]
D10  LED Yellow  [sm_led_0805]
D11  Orange LED  [sm_led_0805]
D12  Green LED  [sm_led_0805]
D13  Green LED  [sm_led_0805]
D14  Green LED  [sm_led_0805]
D15  Blue LED  [sm_led_0805]
D16  Red LED  [sm_led_0805]
Q7  BSS138  [SOT23-3]
Q8  BSS138  [SOT23-3]
Q9  BSS138  [SOT23-3]
Q10  BSS138  [SOT23-3]
Q11  BSS138  [SOT23-3]
Q12  BSS138  [SOT23-3]
Q13  BSS138  [SOT23-3]
Q14  BSS138  [SOT23-3]
R259  150  [SM-7351-RES-0402]
R260  150  [SM-7351-RES-0402]
R261  150  [SM-7351-RES-0402]
R262  0  [SM-7351-RES-0402]
R263  150  [SM-7351-RES-0402]
R264  150  [SM-7351-RES-0402]
R265  150  [SM-7351-RES-0402]
R266  150  [SM-7351-RES-0402]
R267  150  [SM-7351-RES-0402]
R460  100K  [SM-7351-RES-0402]
R461  0  [SM-7351-RES-0402]
R462  100K  [SM-7351-RES-0402]
R463  0  [SM-7351-RES-0402]
R464  100K  [SM-7351-RES-0402]
R465  0  [SM-7351-RES-0402]
R468  0  [SM-7351-RES-0402]
R469  0  [SM-7351-RES-0402]
R470  2.2K  [sm-7351-res-0402]
R472  100K  [SM-7351-RES-0402]
R473  0  [SM-7351-RES-0402]
R474  100K  [SM-7351-RES-0402]
R475  0  [SM-7351-RES-0402]
R476  0  [SM-7351-RES-0402]
R477  100K  [SM-7351-RES-0402]
R478  100K  [SM-7351-RES-0402]
R479  0  [SM-7351-RES-0402]
R480  100K  [SM-7351-RES-0402]
R481  0  [SM-7351-RES-0402]
R483  0  [SM-7351-RES-0402]
R484  2.2K  [sm-7351-res-0402]
R485  2.2K  [sm-7351-res-0402]
R486  0  [SM-7351-RES-0402]
SW4  B3SL  [SW_B3SL-1022P]
SW5  B3SL  [SW_B3SL-1022P]
SW6  B3SL  [SW_B3SL-1022P]
SW7  B3SL  [SW_B3SL-1022P]
SW8  B3SL  [SW_B3SL-1022P]
SW9  B3SL  [SW_B3SL-1022P]
sheet Pg25: JTAG Debug
C7  0.1uF  [SM-7351-CAP-0402]
C51  0.01uF  [SM-7351-CAP-0402]
C320  0.01uF  [SM-7351-CAP-0402]
C337  1uF  [SM-7351-CAP-0603]
J8  ARM JTAG  [hdr2x10-330m]
R29  100  [SM-7351-RES-0402]
R31  10K  [SM-7351-RES-0402]
R38  0  [SM-7351-RES-0402]
R42  0  [SM-7351-RES-0402]
R44  4.7K  [SM-7351-RES-0402]
R58  4.7K  [SM-7351-RES-0402]
R99  10K  [SM-7351-RES-0402]
R161  100K  [SM-7351-RES-0402]
R162  100K  [SM-7351-RES-0402]
R163  100K  [SM-7351-RES-0402]
R164  100K  [SM-7351-RES-0402]
R165  100K  [SM-7351-RES-0402]
R166  100K  [SM-7351-RES-0402]
R167  100K  [SM-7351-RES-0402]
R168  100K  [SM-7351-RES-0402]
R169  100K  [SM-7351-RES-0402]
R299  10K  [SM-7351-RES-0402]
R372  10K  [SM-7351-RES-0402]
R373  10K  [SM-7351-RES-0402]
R374  10K  [SM-7351-RES-0402]
R375  10K  [SM-7351-RES-0402]
R376  10K  [SM-7351-RES-0402]
R377  10K  [SM-7351-RES-0402]
R378  10K  [SM-7351-RES-0402]
R379  10K  [SM-7351-RES-0402]
R380  10K  [SM-7351-RES-0402]
R386  100K  [SM-7351-RES-0402]
R387  100K  [SM-7351-RES-0402]
R388  100K  [SM-7351-RES-0402]
R389  100K  [SM-7351-RES-0402]
R390  100K  [SM-7351-RES-0402]
R391  100K  [SM-7351-RES-0402]
R392  100K  [SM-7351-RES-0402]
R393  100K  [SM-7351-RES-0402]
R394  100K  [SM-7351-RES-0402]
R395  100K  [SM-7351-RES-0402]
R409  10K  [SM-7351-RES-0402]
R410  10K  [SM-7351-RES-0402]
R411  10K  [SM-7351-RES-0402]
R412  10K  [SM-7351-RES-0402]
R413  10K  [SM-7351-RES-0402]
R414  10K  [SM-7351-RES-0402]
R415  10K  [SM-7351-RES-0402]
R416  10K  [SM-7351-RES-0402]
R417  10K  [SM-7351-RES-0402]
R418  10K  [SM-7351-RES-0402]
SW11  DIP Switch 5Pos  [SW291-5M]
SW12  DIP Switch 5Pos  [SW291-5M]
TP1  TP1mm  [tp_smd1mmcircle]
TP2  TP1mm  [tp_smd1mmcircle]
U17  SN74LVC1G04  [SC70-5-43M]
U52  CAT24C256W  [SOIC_8]

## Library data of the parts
M3-M6 = 2M_Screw_4-40_5_8
M7-M10 = 2M_Screw_4-40_1_4
M11-M14 = 2M_Standoff4-40x1_4x5_8Alum
M15-M18 = 2M_RubberFeet_screwno4
PCB1 = 3K_AM437xGPEVMBarePCB
C8 C27 C28 C57 C197 C208-C210 C214 C263 C272 C277 C315 C318 C319 C333 C347 C351-C353 C392 C398 C425 = 1C_10uFCapacitor16V10%0805
C43-C48 C50 C51 C60 C63 C67 C70 C71 C73 C80-C83 C86-C89 C91 C93 C98 C102 C103 C105 C111-C114 C117-C124 C126 C128 C130-C145 C148-C154 C156-C161 C163 C165-C178 C183 C185 C187-C191 C193 C196 C198 C202-C207 C288 C292 C320 C345 C346 C350 C354-C359 C366 C421 C426 = 1C_0.01uFCapacitor16V10%0402
C110 C164 C181 C182 C184 C430 C434 C435 = 1C_1uFCapacitor10V10%0402
C125 = 1C_2.2uF16V10%SMD0805
C194 C201 = 1C_10uFCapacitor6.3V20%0603
FB2-FB9 FB16-FB19 = 1L_FerBead_180ohm200mA
J12 J28 J31 J33 J36 J38 = 2H_Header_2x1
R68 R155 = 1R_0.1ohm0.33W1%Sense0805
R34 R38 R42 R74 R102 R111 R122 R128 R151 R172 R226 R230 R262 R350 R352 R356 R461 R463 R465 R468 R469 R473 R475 R476 R479 R481 R483 R486 = 1R_ZeroOhmResistor1_16W0402
R138 = 1R_11Kohm1_10W1%smd0402
R139 = 1R_523ohm1_16W1%SMD0402
R145 R159 R174 R333 R427 = 1R_ZeroOhmResistor1_16W0603
R305 R307 R317 R328 = 1R_0.05ohm0.5W1%Sense1206
SCKT1 = AM437X_ZDN_Processor_Socket
TP1 TP2 TP22 TP25 = 2H_Testpoint_SMD1mmCircle
C7 C15 C23 C24 C36 C39 C41 C56 C72 C74 C77 C78 C104 C107 C109 C146 C147 C162 C192 C195 C262 C270 C321 C393 C402 C420 = 1C_0.1uFCapacitor16V10%0402
C20 C307 = 1C_0.001uFCapacitor50V5%0402
C21 = 1C_10pFCapacitor50V1%smd0402
C62 C90 C129 C179 = 1C_22uFCapacitor16V10%0805
R31 R35 R39 R41 R99 R124 R126 R129 R146 R299 R372-R380 R396 R397 R409-R418 R424 R425 R430 R432 R434 R438 R441 R444 R448 = 1R_10KOhmResistor1_16W0402
R36 R132 R161-R169 R239 R386-R395 R460 R462 R464 R472 R474 R477 R478 R480 = 1R_100KOhmResistor1_16W0402
R43 = 1R_10ohm1_16W5%smd0402
R53 R56 R63 R65-R67 R71 R73 R78 R81 R88-R90 R300-R303 R314-R316 R319-R323 = 47ohm1_16W1%smd0402
R54 R55 R342 = 1R_49.9OhmResistor1_16W0402
R62 R94 R110 R133 = 1R_240OhmResistor1_16W0402
R112 R116 R141 R205 R206 R429 R431 R433 R437 R440 R445 = 1R_1KOhmResistor1_16W0402
R492 R493 = 1R_2.2KohmResistor1_8W1%0402
U4 = TPS51200
U55 U57 U58 U60 = 1A_MT41K512M8RH
C275 C276 = 1C_22pFCapacitor50V10%SMD0402
C394 C415 = 1C_47uFCapacitor16V20%1206
C397 C432 = 1C_0.1uFCapacitor50V10%0402
D7 = Diode200mA250V
FB10 FB21 FB22 FB25 = 1L_FerriteBead_600mA10ohm
J18 = 2J_ConnectorRJ45_Gigabit
Q6 = 1Q_MOSFET_PChan_FDT434P
R154 R156 R157 R209 R212 R215 R217 R219 R223 R361-R363 = 1R_22OhmResistor1_16W1%0402
R231 = 1R_12.1KohmResistor1_16W1%0402
R44 R58 R237 = 1R_4.7KOhmResistor1_16W0402
R423 R467 = 1R_220ohm1_10W1%smd0402
R451 = 1R_1.5KohmResistor1_16W5%0402
U41 = 1A_KSZ9031RNX
U75 = 1A_SN74LVC1G07
Y6 = 1Y_Crystal25MHzABM3
C199 C225 = 1C_4.7uFCapacitor16V10%0603
C229 C344 = 1C_150uFCapacitor10V10%2917
J11 = 2C_MicroUSBAB
L1 L2 = 1M_ACM2012
Q2 Q7-Q14 = 1Q_MOSFET_NChan_BSS138
R148 = 1R_120Kohm1_16W1%SMD0402
TP12 TP17 = 2H_TestPointThroughHole
U21 U66 = 1A_TPS2051BD
U61 U64 = 1A_TPD4S012
J13 = 2C_Connector_USB_A
U59 = am437x_zdn_GPEVM
D9 D10 = 1F_LED_Yellow
D11 = 1F_LED_Orange
D12-D14 = 1F_LED_Green
D15 = 1F_LED_Blue
D16 = 1F_LED_Red
R259-R261 R263-R267 = 1R_150ohm1_16W1%SMD0402
R470 R484 R485 = 1R_2.2KOhmResistor1_16W0402
SW4-SW9 = 2W_Switch_Pushbuttonsmd
C337 = 1C_1uFCapacitor50V10%0603
J8 = 2H_Header10x2_ARMJTAG
R29 = 1R_100ohm1_16W1%SMD0402
SW11 SW12 = 2W_SwitchDIP5pos_smd
U17 = 1A_SN74LVC1G04
U52 = 1A_CAT24C256W

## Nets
DGND: C7.2 C8.2 C15.2 C20.2 C21.2 C23.2 C24.2 C27.2 C28.2 C36.2 C39.2 C41.2 C43.2 C44.2 C45.2 C46.2 C47.2 C48.2 C50.2 C51.2 C56.2 C57.2 C60.2 C62.2 C63.2 C67.2 C70.2 C71.2 C72.2 C73.2 C77.2 C78.2 C80.2 C81.2 C82.2 C83.2 C86.2 C87.2 C88.2 C89.2 C90.2 C91.2 C93.2 C98.2 C102.2 C103.2 C104.2 C105.2 C109.2 C110.2 C111.2 C112.2 C113.2 C114.2 C117.2 C118.2 C119.2 C120.2 C121.2 C122.2 C125.2 C126.2 C128.2 C129.2 C130.2 C131.2 C132.2 C133.2 C134.2 C135.2 C136.2 C137.2 C138.2 C139.2 C140.2 C141.2 C142.2 C143.2 C144.2 C145.2 C147.2 C148.2 C149.2 C150.2 C151.2 C152.2 C153.2 C154.2 C156.2 C157.2 C158.2 C159.2 C160.2 C161.2 C162.2 C163.2 C164.2 C165.2 C166.2 C167.2 C168.2 C169.2 C170.2 C171.2 C172.2 C173.2 C174.2 C175.2 C176.2 C177.2 C178.2 C179.2 C181.2 C182.2 C183.2 C184.1 C185.2 C187.2 C188.2 C189.2 C190.2 C191.2 C192.2 C193.2 C194.2 C196.2 C197.2 C198.2 C199.2 C201.2 C202.2 C203.2 C204.2 C205.2 C206.2 C207.2 C208.2 C209.2 C210.2 C214.2 C225.2 C229.2(NEG) C262.2 C263.2 C270.2 C272.2 C275.1 C276.1 C277.2 C292.2 C307.2 C315.2 C318.2 C319.2 C320.2 C333.2 C337.2 C344.2(NEG) C345.2 C346.2 C347.2 C350.2 C351.2 C352.2 C353.2 C354.2 C355.2 C356.2 C357.2 C358.2 C359.2 C366.2 C392.2 C393.2 C394.2 C397.1 C398.2 C402.2 C415.2 C420.2 C421.2 C425.2 C426.2 C430.2 C432.1 C434.2 C435.2 FB17.1 FB18.1 J8.4(GND) J8.6(GND) J8.10(GND) J8.12(GND) J8.14(GND) J8.16(GND) J8.18(GND) J8.20(GND) J11.5(GND) J13.4(GND) J18.1 J38.2 Q2.S(SOURCE) Q7.S(SOURCE) Q8.S(SOURCE) Q9.S(SOURCE) Q10.S(SOURCE) Q11.S(SOURCE) Q12.S(SOURCE) Q13.S(SOURCE) Q14.S(SOURCE) R35.1(P1) R39.1(P1) R62.1(P1) R94.1(P1) R102.1(P1) R110.1(P1) R111.1(P1) R129.1(P1) R132.1(P1) R133.1(P1) R138.1(P1) R145.2(P2) R146.2(P2) R148.1(P1) R172.1(P1) R205.1(P1) R206.1(P1) R231.2 R342.1(P1) R372.1(P1) R373.1(P1) R374.1(P1) R375.1(P1) R376.1(P1) R377.1(P1) R378.1(P1) R379.1(P1) R380.1(P1) R397.2(P2) R409.1(P1) R410.1(P1) R411.1(P1) R412.1(P1) R413.1(P1) R414.1(P1) R415.1(P1) R416.1(P1) R417.1(P1) R418.1(P1) R429.1(P1) R431.1(P1) R433.1(P1) R437.1(P1) R440.1(P1) R445.1(P1) R460.1(P1) R462.1(P1) R464.1(P1) R470.1(P1) R472.1(P1) R474.1(P1) R477.1(P1) R478.1(P1) R480.1(P1) R484.1(P1) R485.1(P1) R493.2 U4.4(PGND) U4.8(GND) U4.11(PWRPD) U17.3(GND) U21.1(GND) U41.13(VSS_PS) U41.29(VSS) U41.49(P_GND) U52.1(A0) U52.2(A1) U52.3(A2) U52.4(VSS) U55.A1(VSS) U55.A8(VSS) U55.B1(VSS) U55.B2(VSSQ) U55.B8(VSSQ) U55.C9(VSSQ) U55.D1(VSSQ) U55.D8(VSS) U55.D9(VSSQ) U55.F2(VSS) U55.F8(VSS) U55.J1(VSS) U55.J9(VSS) U55.L1(VSS) U55.L9(VSS) U55.N1(VSS) U55.N9(VSS) U57.A1(VSS) U57.A8(VSS) U57.B1(VSS) U57.B2(VSSQ) U57.B8(VSSQ) U57.C9(VSSQ) U57.D1(VSSQ) U57.D8(VSS) U57.D9(VSSQ) U57.F2(VSS) U57.F8(VSS) U57.J1(VSS) U57.J9(VSS) U57.L1(VSS) U57.L9(VSS) U57.N1(VSS) U57.N9(VSS) U58.A1(VSS) U58.A8(VSS) U58.B1(VSS) U58.B2(VSSQ) U58.B8(VSSQ) U58.C9(VSSQ) U58.D1(VSSQ) U58.D8(VSS) U58.D9(VSSQ) U58.F2(VSS) U58.F8(VSS) U58.J1(VSS) U58.J9(VSS) U58.L1(VSS) U58.L9(VSS) U58.N1(VSS) U58.N9(VSS) U59.A1(GND) U59.A25(GND) U59.AE1(GND) U59.AE25(GND) U59.H15(GND) U59.H18(GND) U59.J9(GND) U59.J12(GND) U59.J15(GND) U59.J17(GND) U59.K9(GND) U59.K11(GND) U59.K12(GND) U59.K14(GND) U59.K15(GND) U59.L8(GND) U59.L9(GND) U59.L11(GND) U59.L15(GND) U59.L17(GND) U59.L18(GND) U59.M10(GND) U59.M11(GND) U59.M13(GND) U59.M15(GND) U59.M16(GND) U59.N10(GND) U59.N11(GND) U59.N12(GND) U59.N13(GND) U59.N14(GND) U59.N15(GND) U59.P8(GND) U59.P9(GND) U59.P10(GND) U59.P11(GND) U59.P12(GND) U59.P13(GND) U59.P14(GND) U59.P15(GND) U59.R12(GND) U59.R15(GND) U59.R17(GND) U59.R18(GND) U59.T12(GND) U59.T15(GND) U59.T17(GND) U59.U8(GND) U59.U9(GND) U59.U10(GND) U59.U11(GND) U59.U12(GND) U59.U13(GND) U59.U14(GND) U59.U16(GND) U59.U17(GND) U59.U18(GND) U59.U19(GND) U59.V9(GND) U59.V10(GND) U59.V11(GND) U59.V12(GND) U59.V13(GND) U59.V14(GND) U59.V18(GND) U59.W23(VSSA_USB) U60.A1(VSS) U60.A8(VSS) U60.B1(VSS) U60.B2(VSSQ) U60.B8(VSSQ) U60.C9(VSSQ) U60.D1(VSSQ) U60.D8(VSS) U60.D9(VSSQ) U60.F2(VSS) U60.F8(VSS) U60.J1(VSS) U60.J9(VSS) U60.L1(VSS) U60.L9(VSS) U60.N1(VSS) U60.N9(VSS) U61.4(GND) U64.4(GND) U66.1(GND) U75.3(GND) ; also on sheet 1 2 3 5 6 7 8 9 10 19 20 21 22 23 24 25 26 27
GND_ETH1: C397.2 C432.2 J18.SHLD1 J18.SHLD2
GNDA_ADC: C123.2 C124.2 R102.2(P2) U59.AC15(VSSA_ADC) ; also on sheet 4
GNDUSB0: FB17.2 J11.S1 J11.S2 J11.S3 J11.S4
GNDUSB1: FB18.2 J13.S1 J13.S2
V1_0BAT: R333.2(P2) ; also on sheet 21
V1_8BAT: R74.1(P1) ; also on sheet 21
V1_8D: R68.1(I1) ; also on sheet 4 5 6 20 21 22 25
V1_8D_AM437X: C119.1 C120.1 C121.1 C130.1 C176.1 C177.1 C178.1 C189.1 C196.1 C197.1 C345.1 C346.1 C347.1 FB2.2 FB3.2 FB4.1 FB5.1 FB6.1 FB7.1 FB8.1 FB9.1 FB16.2 FB19.1 R68.2(I2) R139.1(P1) U59.AD8(VDDS_TPM) U59.C23(VDDS_OSC) U59.F20(VDDS) U59.G6(VDDS) U59.G11(VDDSHV9) U59.H8(VDDSHV11) U59.H9(VDDSHV11) U59.H11(VDDSHV9) U59.H12(VDDS) U59.P19(VDDS) U59.U21(VDDA1P8V_USB1) U59.W15(VDDS) U59.Y19(VDDS)
V3_3D: C8.1 C51.1 C320.1 FB10.1 J8.1(VTREF) J8.2(VSPLY) R31.2(P2) R36.2(P2) R44.2(P2) R58.2(P2) R99.2(P2) R124.1(P1) R126.2(P2) R155.1(I1) R161.2(P2) R162.2(P2) R163.2(P2) R164.2(P2) R165.2(P2) R166.2(P2) R167.2(P2) R168.2(P2) R169.2(P2) R299.2(P2) R386.2(P2) R387.2(P2) R388.2(P2) R389.2(P2) R390.2(P2) R391.2(P2) R392.2(P2) R393.2(P2) R394.2(P2) R395.2(P2) R396.1(P1) R423.2 R427.2(P2) R467.2 U4.10(VIN) U17.5(VCC) U52.8(VCC) ; also on sheet 1 2 3 5 6 7 8 9 10 19 20 21 22 23 24 25 27
V3_3D_AM437X: C133.1 C158.1 C165.1 C170.1 C202.1 C203.1 C204.1 C205.1 C206.1 C207.1 C208.1 C209.1 C210.1 C350.1 C351.1 C352.1 C353.1 C354.1 C355.1 C356.1 C357.1 C358.1 C359.1 R122.2(P2) R155.2(I2) U59.F16(VDDSHV7) U59.F22(VDDSHV5) U59.G10(VDDSHV10) U59.G13(VDDSHV8) U59.G14(VDDSHV8) U59.G16(VDDSHV6) U59.G17(VDDSHV6) U59.H10(VDDSHV10) U59.H17(VDDSHV6) U59.J7(VDDSHV1) U59.J8(VDDSHV1) U59.J18(VDDSHV3) U59.K17(VDDSHV3) U59.K18(VDDSHV3) U59.N18(VDDSHV3) U59.N19(VDDSHV3) U59.P18(VDDSHV3) U59.V16(VDDSHV2) U59.V17(VDDSHV2) U59.W16(VDDSHV2) U59.W18(VDDSHV3)
V5_0D: U21.2(IN) U21.3(IN) U66.2(IN) U66.3(IN) ; also on sheet 3 21
VBAT: R259.2(P2) R260.2(P2) R261.2(P2) R263.2(P2) R264.2(P2) R265.2(P2) R266.2(P2) R267.2(P2) ; also on sheet 1 3 4 5 9 10 20 21 24 27
VBUS0_OTG_CAP: C344.1(POS) J12.2
VBUS1_OTG_CAP: C229.1(POS) J36.2 R174.2(P2)
VDD_CORE: C128.1 C137.1 C138.1 C140.1 C142.1 C150.1 C153.1 C156.1 C333.1 J31.1 R328.2(I2) U59.AD9(VDD_TPM) U59.J10(VDD_CORE) U59.J11(VDD_CORE) U59.L12(VDD_CORE) U59.L14(VDD_CORE) U59.M9(VDD_CORE) U59.M12(VDD_CORE) U59.M14(VDD_CORE) U59.N9(VDD_CORE) U59.N16(VDD_CORE) U59.N17(VDD_CORE) U59.P16(VDD_CORE) U59.P17(VDD_CORE) U59.R9(VDD_CORE) U59.R11(VDD_CORE) U59.R14(VDD_CORE) U59.T9(VDD_CORE) U59.T11(VDD_CORE) U59.T14(VDD_CORE) U59.T18(VDD_CORE) U59.T19(VDD_CORE) U59.U15(VDD_CORE) U59.V15(VDD_CORE) U59.W12(VDD_CORE) U59.W13(VDD_CORE)
VDD_MPU: C57.1 C88.1 C154.1 C157.1 C160.1 C163.1 J28.1 R317.2(I2) U59.H13(VDD_MPU) U59.H14(VDD_MPU) U59.H16(VDD_MPU) U59.J13(VDD_MPU) U59.J14(VDD_MPU) U59.J16(VDD_MPU) U59.K19(VDD_MPU) U59.K20(VDD_MPU) U59.L19(VDD_MPU) U59.L20(VDD_MPU) U59.M17(VDD_MPU) U59.M18(VDD_MPU)
VDDA1_8_USB0: C125.1 C131.1 FB4.2 U59.W21(VDDA1P8V_USB0)
VDDA1P8_PMLDO: R159.1(P1) U59.D6(VDDA1P8_PMLDO)
VDDA3_3_USB: C143.1 R122.1(P1) U59.U20(VDDA_3P3V_USB1) U59.W20(VDDA_3P3V_USB0)
VDDA3P3_PMLDO: R145.1(P1) U59.F8(VDDA3P3_PMLDO)
VDDA_ADC: C123.1 FB2.1 U59.AB12(VDDA_TS_ADC) ; also on sheet 4
VDDA_MC_ADC: C124.1 FB3.1 U59.Y16(VDDA_MC_ADC) ; also on sheet 4
VDDR_VREF: C15.1 C39.1 C72.1 C74.2 C77.1 C104.1 C107.2 C109.1 C146.2 C147.1 C162.1 C192.1 C195.2 U4.6(REFOUT) U55.E1(VREFDQ) U55.J8(VREFCA) U57.E1(VREFDQ) U57.J8(VREFCA) U58.E1(VREFDQ) U58.J8(VREFCA) U60.E1(VREFDQ) U60.J8(VREFCA)
VDDR_VTT: C24.1 C28.1 C36.1 C41.1 C56.1 C78.1 C318.1 C319.1 R43.2(P2) R53.1(P1) R56.1(P1) R63.1(P1) R65.1(P1) R66.1(P1) R67.1(P1) R71.1(P1) R73.1(P1) R78.1(P1) R81.1(P1) R88.1(P1) R89.1(P1) R90.1(P1) R300.1(P1) R301.1(P1) R302.1(P1) R303.1(P1) R314.1(P1) R315.1(P1) R316.1(P1) R319.1(P1) R320.1(P1) R321.1(P1) R322.1(P1) R323.1(P1) U4.3(VO)
VDDS_CTM: FB16.1 U59.AD12(VDDS_CTM)
VDDS_DDR: C23.1 C27.1 C43.1 C44.1 C45.1 C46.1 C47.1 C48.1 C50.1 C60.1 C62.1 C63.1 C67.1 C70.1 C71.1 C73.1 C74.1 C80.1 C81.1 C82.1 C83.1 C86.1 C87.1 C89.1 C90.1 C91.1 C93.1 C98.1 C102.1 C103.1 C105.1 C107.1 C111.1 C112.1 C113.1 C114.1 C117.1 C122.1 C126.1 C129.1 C132.1 C135.1 C139.1 C144.1 C145.1 C146.1 C148.1 C166.1 C167.1 C168.1 C169.1 C173.1 C174.1 C175.1 C179.1 C183.1 C185.1 C187.1 C190.1 C191.1 C193.1 C195.1 C307.1 C315.1 C321.2 R41.2(P2) R141.2(P2) R307.2(I2) U4.2(VLDOIN) U55.A2(VDD) U55.A9(VDD) U55.B9(VDDQ) U55.C1(VDDQ) U55.D7(VDD) U55.E2(VDDQ) U55.E9(VDDQ) U55.G2(VDD) U55.G8(VDD) U55.K1(VDD) U55.K9(VDD) U55.M1(VDD) U55.M9(VDD) U57.A2(VDD) U57.A9(VDD) U57.B9(VDDQ) U57.C1(VDDQ) U57.D7(VDD) U57.E2(VDDQ) U57.E9(VDDQ) U57.G2(VDD) U57.G8(VDD) U57.K1(VDD) U57.K9(VDD) U57.M1(VDD) U57.M9(VDD) U58.A2(VDD) U58.A9(VDD) U58.B9(VDDQ) U58.C1(VDDQ) U58.D7(VDD) U58.E2(VDDQ) U58.E9(VDDQ) U58.G2(VDD) U58.G8(VDD) U58.K1(VDD) U58.K9(VDD) U58.M1(VDD) U58.M9(VDD) U60.A2(VDD) U60.A9(VDD) U60.B9(VDDQ) U60.C1(VDDQ) U60.D7(VDD) U60.E2(VDDQ) U60.E9(VDDQ) U60.G2(VDD) U60.G8(VDD) U60.K1(VDD) U60.K9(VDD) U60.M1(VDD) U60.M9(VDD)
VDDS_PLL_CORE_LCD: C151.1 FB5.2 U59.N21(VDDS_PLL_CORE_LCD)
VDDS_PLL_DDR: C172.1 FB8.2 U59.G5(VDDS_PLL_DDR)
VDDS_PLL_MPU: C171.1 FB9.2 U59.E17(VDDS_PLL_MPU)
VDDS_SRAM_CORE_BG: C194.1 FB7.2 U59.F13(VDDS_SRAM_CORE_BG)
VDDS_SRAM_MPU_BB: C201.1 FB19.2 U59.F14(VDDS_SRAM_MPU_BB)
AM437X_KEY_PWRA: R483.2(P2) ; also on sheet 24
AM437X_KEY_PWRB: R486.2(P2) ; also on sheet 24
AM437X_KEY_SCN0: R262.2(P2) ; also on sheet 24
AM437X_KEY_SCN1: R469.2(P2) ; also on sheet 24
AM437X_KEY_SCN2: R468.2(P2) ; also on sheet 24
AM437X_LCD_AC_BIAS_EN: R168.1(P1) R373.2(P2) ; also on sheet 5
AM437X_LCD_DATA0: R391.1(P1) SW12.10 ; also on sheet 5
AM437X_LCD_DATA1: R392.1(P1) SW12.9 ; also on sheet 5
AM437X_LCD_DATA2: R393.1(P1) SW12.8 ; also on sheet 5
AM437X_LCD_DATA3: R394.1(P1) SW12.7 ; also on sheet 5
AM437X_LCD_DATA4: R395.1(P1) SW12.6 ; also on sheet 5
AM437X_LCD_DATA5: R386.1(P1) SW11.10 ; also on sheet 5
AM437X_LCD_DATA6: R387.1(P1) SW11.9 ; also on sheet 5
AM437X_LCD_DATA7: R163.1(P1) R378.2(P2) ; also on sheet 5
AM437X_LCD_DATA8: R166.1(P1) R375.2(P2) ; also on sheet 5
AM437X_LCD_DATA9: R388.1(P1) SW11.8 ; also on sheet 5
AM437X_LCD_DATA10: R164.1(P1) R377.2(P2) ; also on sheet 5
AM437X_LCD_DATA11: R165.1(P1) R376.2(P2) ; also on sheet 5
AM437X_LCD_DATA12: R389.1(P1) SW11.7 ; also on sheet 5
AM437X_LCD_DATA13: R390.1(P1) SW11.6 ; also on sheet 5
AM437X_LCD_DATA14: R162.1(P1) R379.2(P2) ; also on sheet 5
AM437X_LCD_DATA15: R161.1(P1) R380.2(P2) ; also on sheet 5
AM437X_LCD_HSYNC: R167.1(P1) R374.2(P2) ; also on sheet 5
AM437X_LCD_VSYNC: R169.1(P1) R372.2(P2) ; also on sheet 5
AM437X_RGMII1_RXCLK: R223.2(P2) U59.D13(GMII1_RXCLK/RGMII1_RCLK)
AM437X_RGMII1_RXCTL: R219.2(P2) U59.A15(GMII1_RXDV/RGMII1_RCTL)
AM437X_RGMII1_RXD0: R217.2(P2) U59.F17(GMII1_RXD0/RGMII1_RD0)
AM437X_RGMII1_RXD1: R215.2(P2) U59.B16(GMII1_RXD1/RGMII1_RD1)
AM437X_RGMII1_RXD2: R212.2(P2) U59.E16(GMII1_RXD2/RGMII1_RD2)
AM437X_RGMII1_RXD3: R209.2(P2) U59.C14(GMII1_RXD3/RGMII1_RD3)
AM437X_RGMII1_TXCLK: R157.2(P2) U59.D14(GMII1_TXCLK/RGMII1_TCLK)
AM437X_RGMII1_TXCTL: R363.2(P2) U59.A13(GMII1_TXEN/RGMII1_TCTL)
AM437X_RGMII1_TXD0: R361.2(P2) U59.B15(GMII1_TXD0/RGMII1_TD0)
AM437X_RGMII1_TXD1: R362.2(P2) U59.A14(GMII1_TXD1/RGMII1_TD1)
AM437X_RGMII1_TXD2: R156.2(P2) U59.C13(GMII1_TXD2/RGMII1_TD2)
AM437X_RGMII1_TXD3: R154.2(P2) U59.C16(GMII1_TXD3/RGMII1_TD3)
AM437X_STATUS_LED0: R476.2(P2) ; also on sheet 24
AM437X_STATUS_LED1: R475.2(P2) ; also on sheet 10 24
AM437X_STATUS_LED2: R473.2(P2) ; also on sheet 10 24
AM437X_STATUS_LED3: R465.2(P2) ; also on sheet 24
AM437X_STATUS_LED4: R463.2(P2) ; also on sheet 24
AM437X_STATUS_LED5: R461.2(P2) ; also on sheet 24
AM437X_STATUS_LED6: R481.2(P2) ; also on sheet 24
AM437X_STATUS_LED7: R479.2(P2) ; also on sheet 24
AM437X_USB0_CE: TP12.1 U59.W22(USB0_CE)
AM437X_USB0_DM: L1.2 U59.W24(USB0_DM)
AM437X_USB0_DP: L1.1 U59.W25(USB0_DP)
AM437X_USB0_ID: R350.2(P2) U59.U24(USB0_ID)
AM437X_USB0_VBUS: R112.2(P2) U59.U23(USB0_VBUS)
AM437X_USB1_CE: TP17.1 U59.U22(USB1_CE)
AM437X_USB1_DM: L2.2 U59.V25(USB1_DM)
AM437X_USB1_DP: L2.1 U59.V24(USB1_DP)
AM437X_USB1_DRVVBUS: R356.2(P2) U59.F25(USB1_DRVVBUS)
AM437X_USB1_ID: R352.2(P2) U59.U25(USB1_ID)
AM437X_USB1_VBUS: R116.2(P2) U59.T25(USB1_VBUS)
AM437X_VDDR_VREF: C141.1 C288.2 R492.2 R493.1 U59.T6(DDR_VREF)
CAP_VBB_MPU: C164.1 U59.F19(CAP_VBB_MPU)
CAP_VDD_SRAM_CORE: C181.1 U59.E13(CAP_VDD_SRAM_CORE)
CAP_VDD_SRAM_MPU: C182.1 U59.E14(CAP_VDD_SRAM_MPU)
DDR_A0: R73.2(P2) U55.K3(A0) U57.K3(A0) U58.K3(A0) U59.N1(DDR_A0) U60.K3(A0)
DDR_A1: R66.2(P2) U55.L7(A1) U57.L7(A1) U58.L7(A1) U59.L1(DDR_A1) U60.L7(A1)
DDR_A2: R316.2(P2) U55.L3(A2) U57.L3(A2) U58.L3(A2) U59.L2(DDR_A2) U60.L3(A2)
DDR_A3: R321.2(P2) U55.K2(A3) U57.K2(A3) U58.K2(A3) U59.P2(DDR_A3) U60.K2(A3)
DDR_A4: R301.2(P2) U55.L8(A4) U57.L8(A4) U58.L8(A4) U59.P1(DDR_A4) U60.L8(A4)
DDR_A5: R320.2(P2) U55.L2(A5) U57.L2(A5) U58.L2(A5) U59.R5(DDR_A5) U60.L2(A5)
DDR_A6: R302.2(P2) U55.M8(A6) U57.M8(A6) U58.M8(A6) U59.R4(DDR_A6) U60.M8(A6)
DDR_A7: R78.2(P2) U55.M2(A7) U57.M2(A7) U58.M2(A7) U59.R3(DDR_A7) U60.M2(A7)
DDR_A8: R303.2(P2) U55.N8(A8) U57.N8(A8) U58.N8(A8) U59.R2(DDR_A8) U60.N8(A8)
DDR_A9: R71.2(P2) U55.M3(A9) U57.M3(A9) U58.M3(A9) U59.R1(DDR_A9) U60.M3(A9)
DDR_A10: R53.2(P2) U55.H7(A10/AP) U57.H7(A10/AP) U58.H7(A10/AP) U59.M6(DDR_A10) U60.H7(A10/AP)
DDR_A11: R65.2(P2) U55.M7(A11) U57.M7(A11) U58.M7(A11) U59.T5(DDR_A11) U60.M7(A11)
DDR_A12: R63.2(P2) U55.K7(A12/~{BC}) U57.K7(A12/~{BC}) U58.K7(A12/~{BC}) U59.T4(DDR_A12) U60.K7(A12/~{BC})
DDR_A13: R319.2(P2) U55.N3(A13) U57.N3(A13) U58.N3(A13) U59.N5(DDR_A13) U60.N3(A13)
DDR_A14: R314.2(P2) U55.N7(A14) U57.N7(A14) U58.N7(A14) U59.T3(DDR_A14) U60.N7(A14)
DDR_A15: R67.2(P2) U55.J7(A15) U57.J7(A15) U58.J7(A15) U59.T2(DDR_A15) U60.J7(A15)
DDR_BA0: R322.2(P2) U55.J2(BA0) U57.J2(BA0) U58.J2(BA0) U59.K1(DDR_BA0) U60.J2(BA0)
DDR_BA1: R300.2(P2) U55.K8(BA1) U57.K8(BA1) U58.K8(BA1) U59.K2(DDR_BA1) U60.K8(BA1)
DDR_BA2: R81.2(P2) U55.J3(BA2) U57.J3(BA2) U58.J3(BA2) U59.K3(DDR_BA2) U60.J3(BA2)
DDR_CASN: R90.2(P2) U55.G3(CASn) U57.G3(CASn) U58.G3(CASn) U59.N3(DDR_CASn) U60.G3(CASn)
DDR_CKE: R56.2(P2) R128.1(P1) U55.G9(CKE) U57.G9(CKE) U58.G9(CKE) U60.G9(CKE)
DDR_CKE0: R128.2(P2) R129.2(P2) U59.M3(DDR_CKE0)
DDR_CLK: R55.2(P2) U55.F7(CK) U57.F7(CK) U58.F7(CK) U59.M2(DDR_CK) U60.F7(CK)
DDR_CLKn: R54.2(P2) U55.G7(CKn) U57.G7(CKn) U58.G7(CKn) U59.M1(DDR_CKn) U60.G7(CKn)
DDR_CS0n: R89.2(P2) U55.H2(CSn) U57.H2(CSn) U58.H2(CSn) U59.M5(DDR_CSN0) U60.H2(CSn)
DDR_D0: U59.E3(DDR_D0) U60.B3(DQ0)
DDR_D1: U59.E2(DDR_D1) U60.C7(DQ1)
DDR_D2: U59.E1(DDR_D2) U60.C2(DQ2)
DDR_D3: U59.F3(DDR_D3) U60.C8(DQ3)
DDR_D4: U59.G4(DDR_D4) U60.E3(DQ4)
DDR_D5: U59.G3(DDR_D5) U60.E8(DQ5)
DDR_D6: U59.G2(DDR_D6) U60.D2(DQ6)
DDR_D7: U59.G1(DDR_D7) U60.E7(DQ7)
DDR_D8: U58.B3(DQ0) U59.H1(DDR_D8)
DDR_D9: U58.C7(DQ1) U59.J6(DDR_D9)
DDR_D10: U58.C2(DQ2) U59.J5(DDR_D10)
DDR_D11: U58.C8(DQ3) U59.J4(DDR_D11)
DDR_D12: U58.E3(DQ4) U59.J3(DDR_D12)
DDR_D13: U58.E8(DQ5) U59.K6(DDR_D13)
DDR_D14: U58.D2(DQ6) U59.K5(DDR_D14)
DDR_D15: U58.E7(DQ7) U59.K4(DDR_D15)
DDR_D16: U57.B3(DQ0) U59.V5(DDR_D16)
DDR_D17: U57.C7(DQ1) U59.V4(DDR_D17)
DDR_D18: U57.C2(DQ2) U59.V3(DDR_D18)
DDR_D19: U57.C8(DQ3) U59.V2(DDR_D19)
DDR_D20: U57.E3(DQ4) U59.V1(DDR_D20)
DDR_D21: U57.E8(DQ5) U59.W4(DDR_D21)
DDR_D22: U57.D2(DQ6) U59.W5(DDR_D22)
DDR_D23: U57.E7(DQ7) U59.W6(DDR_D23)
DDR_D24: U55.B3(DQ0) U59.Y2(DDR_D24)
DDR_D25: U55.C7(DQ1) U59.Y3(DDR_D25)
DDR_D26: U55.C2(DQ2) U59.Y4(DDR_D26)
DDR_D27: U55.C8(DQ3) U59.AA3(DDR_D27)
DDR_D28: U55.E3(DQ4) U59.AB2(DDR_D28)
DDR_D29: U55.E8(DQ5) U59.AB1(DDR_D29)
DDR_D30: U55.D2(DQ6) U59.AC1(DDR_D30)
DDR_D31: U55.E7(DQ7) U59.AC2(DDR_D31)
DDR_DQM0: U59.F4(DDR_DQM0) U60.B7(DM)
DDR_DQM1: U58.B7(DM) U59.H2(DDR_DQM1)
DDR_DQM2: U57.B7(DM) U59.V6(DDR_DQM2)
DDR_DQM3: U55.B7(DM) U59.Y1(DDR_DQM3)
DDR_DQS0: U59.F2(DDR_DQS0) U60.C3(DQS)
DDR_DQS1: U58.C3(DQS) U59.J2(DDR_DQS1)
DDR_DQS2: U57.C3(DQS) U59.W1(DDR_DQS2)
DDR_DQS3: U55.C3(DQS) U59.AA1(DDR_DQS3)
DDR_DQSN0: U59.F1(DDR_DQS0n) U60.D3(DQSn)
DDR_DQSN1: U58.D3(DQSn) U59.J1(DDR_DQS1n)
DDR_DQSN2: U57.D3(DQSn) U59.W2(DDR_DQS2n)
DDR_DQSN3: U55.D3(DQSn) U59.AA2(DDR_DQS3n)
DDR_ODT: R323.2(P2) U55.G1(ODT) U57.G1(ODT) U58.G1(ODT) U59.U1(DDR_ODT0) U60.G1(ODT)
DDR_RASN: R88.2(P2) U55.F3(RASn) U57.F3(RASn) U58.F3(RASn) U59.N2(DDR_RASn) U60.F3(RASn)
DDR_RESETn: R141.1(P1) U55.N2(RESETn) U57.N2(RESETn) U58.N2(RESETn) U59.T1(DDR_RESETn) U60.N2(RESETn)
DDR_WEn: R315.2(P2) U55.H3(WEn) U57.H3(WEn) U58.H3(WEn) U59.N4(DDR_WEn) U60.H3(WEn)
EMU_RSTn: C7.1 J8.15(nSRST) R29.1(P1) R31.1(P1)
ETH1_LDO_O: Q6.G(GATE) U41.43(LDO_O)
ETH1_RESETn: C277.1 D7.2(Anode) R239.1(P1) U41.42(RESET_N) U75.4(Y)
ETH1_RXCLK: R223.1(P1) R444.2(P2) R445.2(P2) U41.35(RX_CLK)
ETH1_RXD0: R217.1(P1) R437.2(P2) R438.2(P2) U41.32(RXD0)
ETH1_RXD1: R215.1(P1) R433.2(P2) R434.2(P2) U41.31(RXD1)
ETH1_RXD2: R212.1(P1) R431.2(P2) R432.2(P2) U41.28(RXD2)
ETH1_RXD3: R209.1(P1) R429.2(P2) R430.2(P2) U41.27(RXD3)
ETH1_RXDV: R219.1(P1) R440.2(P2) R441.2(P2) U41.33(RX_DV)
ETH1_TXCLK: R157.1(P1) U41.24(GTX_CLK)
ETH1_TXD0: R361.1(P1) U41.19(TXD0)
ETH1_TXD1: R362.1(P1) U41.20(TXD1)
ETH1_TXD2: R156.1(P1) U41.21(TXD2)
ETH1_TXD3: R154.1(P1) U41.22(TXD3)
ETH1_TXEN: R363.1(P1) U41.25(TX_EN)
ETH_MDIO_CLK: R226.2(P2) R448.2(P2) U59.B17(MDIO_CLK/MDIO_CLK)
ETH_MDIO_DATA: R230.2(P2) R451.1(P1) U59.A17(MDIO_DATA/MDIO_DATA)
ETHER1_D0N: J18.10 U41.3(TXRXM_A)
ETHER1_D0P: J18.9 U41.2(TXRXP_A)
ETHER1_D1N: J18.8 U41.6(TXRXM_B)
ETHER1_D1P: J18.7 U41.5(TXRXP_B)
ETHER1_D2N: J18.6 U41.8(TXRXM_C)
ETHER1_D2P: J18.5 U41.7(TXRXP_C)
ETHER1_D3N: J18.4 U41.11(TXRXM_D)
ETHER1_D3P: J18.3 U41.10(TXRXP_D)
GPIO_VTTEN: R34.2(P2) ; also on sheet 24
I2C0_SCL: U52.6(SCL) ; also on sheet 1 21
I2C0_SDA: U52.5(SDA) ; also on sheet 1 21
JTAG_DBGACK: J8.19(DBGACK) TP2.1
JTAG_DBGRQ: J8.17(DBGRQ) TP1.1
JTAG_TCK: R38.2(P2) R42.2(P2) U59.AA25(JTAG_TCK) ; also on sheet 10
JTAG_TDI: J8.5(TDI) U59.Y20(JTAG_TDI) ; also on sheet 10
JTAG_TDO: J8.13(TDO) U59.AA24(JTAG_TDO) ; also on sheet 10
JTAG_TMS: J8.7(TMS) R44.1(P1) U59.Y24(JTAG_TMS) ; also on sheet 10
JTAG_TRSTn: J8.3(nTRST) R58.1(P1) U59.Y25(JTAG_TRSTn) ; also on sheet 10
JTAGPOD_PRES: U17.4(Y) ; also on sheet 10
KEYPAD_PWRA: R483.1(P1) SW4.1 SW4.2 SW5.1 SW5.2 SW6.1 SW6.2
KEYPAD_PWRB: R486.1(P1) SW7.1 SW7.2 SW8.1 SW8.2 SW9.1 SW9.2
KEYPAD_SCN0: C435.1 R262.1(P1) R485.2(P2) SW4.3 SW4.4 SW7.3 SW7.4
KEYPAD_SCN1: C434.1 R469.1(P1) R484.2(P2) SW5.3 SW5.4 SW8.3 SW8.4
KEYPAD_SCN2: C430.1 R468.1(P1) R470.2(P2) SW6.3 SW6.4 SW9.3 SW9.4
PHY1_LED_ACTn: J18.12 R205.2(P2) R425.2(P2) U41.17(LED1_/_PME_N1)
PHY1_LED_LINKn: J18.13 R206.2(P2) R424.2(P2) U41.15(LED2)
PM_AM437X_V1_8DN: R68.4(SENS2) ; also on sheet 19
PM_AM437X_V1_8DP: R68.3(SENS1) ; also on sheet 19
PM_AM437X_V3_3DN: R155.4(SENS2) ; also on sheet 19
PM_AM437X_V3_3DP: R155.3(SENS1) ; also on sheet 19
PM_VDDCOREN: R328.4(SENS2) ; also on sheet 19
PM_VDDCOREP: R328.3(SENS1) ; also on sheet 19
PM_VDDMPUN: R317.4(SENS2) ; also on sheet 19
PM_VDDMPUP: R317.3(SENS1) ; also on sheet 19
PM_VDDSAM437XDDRN: R305.4(SENS2) ; also on sheet 19
PM_VDDSAM437XDDRP: R305.3(SENS1) ; also on sheet 19
PM_VDDSDDRN: R307.4(SENS2) ; also on sheet 19
PM_VDDSDDRP: R307.3(SENS1) ; also on sheet 19
RTCK: J8.11(RTCK) R38.1(P1)
SYS_RESETn: R29.2(P2) U75.2(A) ; also on sheet 3 5 10 22
TCK: J8.9(TCK) R42.1(P1)
USB0_CONN_DM: J11.2(DM) L1.3 U61.2(D-)
USB0_CONN_DP: J11.3(DP) L1.4 U61.1(D+)
USB0_ID: J11.4(ID) R148.2(P2) R350.1(P1) U61.3(ID)
USB0_OVRCURn: R124.2(P2) U21.5(~{OC})
USB0_VBUS_DET: Q2.D(DRAIN) R126.1(P1) ; also on sheet 24
USB0_VBUS_EN: R146.1(P1) R151.1(P1) U21.4(EN)
USB1_CONN_DM: J13.2(DM) L2.3 U64.2(D-)
USB1_CONN_DP: J13.3(DP) L2.4 U64.1(D+)
USB1_ID: R172.2(P2) R352.1(P1) U64.3(ID)
USB1_OVRCURn: R396.2(P2) U66.5(~{OC})
USB1_VBUS_EN: R356.1(P1) R397.1(P1) U66.4(EN)
VAM437X_DDR: C134.1 C136.1 C149.1 C152.1 C159.1 C161.1 C188.1 C214.1 C288.1 R305.2(I2) R492.1 U59.K7(VDD_DDR) U59.K8(VDD_DDR) U59.M7(VDD_DDR) U59.M8(VDD_DDR) U59.N7(VDD_DDR) U59.N8(VDD_DDR) U59.R6(VDD_DDR) U59.R7(VDD_DDR) U59.R8(VDD_DDR) U59.T7(VDD_DDR) U59.T8(VDD_DDR) U59.V7(VDD_DDR) U59.V8(VDD_DDR)
VDCDC1: J31.2 R328.1(I1) ; also on sheet 19 21
VDCDC2: J28.2 R317.1(I1) ; also on sheet 19 21
VDCDC3: R307.1(I1) ; also on sheet 21
VETH1_AVDDH: C262.1 C263.1 C415.1 FB10.2 Q6.S(SOURCE) U41.1(AVDDH) U41.12(AVDDH) U41.47(AVDDH)
VETH1_AVDDL: C270.1 C272.1 FB25.2 U41.4(AVDDL) U41.9(AVDDL)
VETH1_AVDDL_PLL: C420.1 C421.1 C425.1 FB22.2 U41.44(AVDDL_PLL)
VETH1_AVDDL_PMOS: C394.1 FB21.1 FB22.1 FB25.1 Q6.D1(DRAIN1) Q6.D2(DRAIN2)
VETH1_DVDDH: C398.1 C402.1 C426.1 D7.1(Cathode) R237.2(P2) R239.2(P2) R424.1(P1) R425.1(P1) R427.1(P1) R430.1(P1) R432.1(P1) R434.1(P1) R438.1(P1) R441.1(P1) R444.1(P1) R448.1(P1) R451.2(P2) U41.16(DVDDH) U41.34(DVDDH) U41.40(DVDDH) U75.5(VCC)
VETH1_DVDDL: C392.1 C393.1 FB21.2 U41.14(DVDDL) U41.18(DVDDL) U41.23(DVDDL) U41.26(DVDDL) U41.30(DVDDL) U41.39(DVDDL)
VLS1: R305.1(I1) ; also on sheet 21
VUSB_VBUS0: C198.1 C199.1 J11.1(VBUS) J12.1 Q2.G(GATE) R112.1(P1) R132.2(P2) U21.6(OUT) U21.7(OUT) U21.8(OUT) U61.6(VBUS) ; also on sheet 21
VUSB_VBUS1: C225.1 C366.1 J13.1(VBUS) J36.1 R116.1(P1) R174.1(P1) U64.6(VBUS) U66.6(OUT) U66.7(OUT) U66.8(OUT)
N11217419: C321.1 R54.1(P1) R55.1(P1)
N12081710: J38.1 R237.1(P1) U41.38(INT_N_/_PME_N2)
N12081804: C276.2 U41.46(XI) Y6.2
N12081808: C275.2 U41.45(XO) Y6.1
N12123192: J18.11 R423.1
N12123204: J18.14 R467.1
N12138752: R226.1(P1) U41.36(MDC)
N12138831: R230.1(P1) U41.37(MDIO)
N12138943: R231.1 U41.48(ISET)
N12139138: TP25.1 U41.41(CLK125_NDO)
N12595082: R342.2(P2) U59.AC3(DDR_VTP)
N14122798: Q12.G(GATE) R476.1(P1) R477.2(P2)
N14122802: Q11.G(GATE) R474.2(P2) R475.1(P1)
N14122806: Q10.G(GATE) R472.2(P2) R473.1(P1)
N14122814: Q9.G(GATE) R464.2(P2) R465.1(P1)
N14123228: D12.1(Cathode) Q12.D(DRAIN)
N14123236: D12.2(Anode) R263.1(P1)
N14123256: D13.1(Cathode) Q11.D(DRAIN)
N14123268: D13.2(Anode) R264.1(P1)
N14123284: D14.2(Anode) R265.1(P1)
N14123288: D14.1(Cathode) Q10.D(DRAIN)
N14123296: D9.1(Cathode) Q9.D(DRAIN)
N14123312: D9.2(Anode) R259.1(P1)
N15652211: Q8.G(GATE) R462.2(P2) R463.1(P1)
N15652215: Q7.G(GATE) R460.2(P2) R461.1(P1)
N15652219: Q14.G(GATE) R480.2(P2) R481.1(P1)
N15652227: Q13.G(GATE) R478.2(P2) R479.1(P1)
N15652267: D10.1(Cathode) Q8.D(DRAIN)
N15652281: D10.2(Anode) R260.1(P1)
N15652301: D11.1(Cathode) Q7.D(DRAIN)
N15652313: D11.2(Anode) R261.1(P1)
N15652329: D15.2(Anode) R266.1(P1)
N15652333: D15.1(Cathode) Q14.D(DRAIN)
N15652341: D16.1(Cathode) Q13.D(DRAIN)
N15652357: D16.2(Anode) R267.1(P1)
N15781308: R133.2(P2) U60.H8(ZQ)
N15810701: R110.2(P2) U58.H8(ZQ)
N15813652: R94.2(P2) U57.H8(ZQ)
N15822328: R34.1(P1) R35.2(P2) U4.7(EN)
N15822442: R36.1(P1) U4.9(PGOOD)
N15822464: C21.1 R43.1(P1) U4.5(VOSNS)
N15822844: C20.1 R39.2(P2) R41.1(P1) U4.1(REFIN)
N15826249: R62.2(P2) U55.H8(ZQ)
N17034041: R409.2(P2) SW12.1
N17034069: R410.2(P2) SW12.2
N17034107: R411.2(P2) SW12.3
N17034117: R412.2(P2) SW12.4
N17034161: R413.2(P2) SW12.5
N17345501: R414.2(P2) SW11.1
N17345515: R415.2(P2) SW11.2
N17345519: R416.2(P2) SW11.3
N17345529: R417.2(P2) SW11.4
N17345551: R418.2(P2) SW11.5
N17462072: C292.1 FB6.2 U59.E23(VDDS_CLKOUT)
N17463583: TP22.1 U59.D20(VDD_MPU_MON)
N17514704: C337.1 J8.8(GND) R99.1(P1) U17.2(A)
N17515933: R151.2(P2) U59.G21(USB0_DRVVBUS)
N17670442: R111.2(P2) U59.AA23(TEST_EN)
N17687132: C184.2 J33.1 R138.2(P2) R139.2(P2)
N17688718: J33.2 U59.P21(VPP)
N17695349: C110.1 R333.1(P1) U59.AD3(CAP_VDD_RTC)
N17696295: C118.1 R74.2(P2) U59.AD5(VDDS_RTC)
N18136628: R299.1(P1) U52.7(WP)

Not connected (* = marked no-connect by the designer): J18 2; R159 2(P2)*; SCKT1 MCH1* MCH2* MCH3* MCH4*; U17 1(NC)*; U55 A3(NU) A7(NF/TDQS#) F1(NU) F9(NU) H1(NU) H9(NU); U57 A3(NU) A7(NF/TDQS#) F1(NU) F9(NU) H1(NU) H9(NU); U58 A3(NU) A7(NF/TDQS#) F1(NU) F9(NU) H1(NU) H9(NU); U59 H21(TESTOUT) M4(DDR_CSN1) N6(DDR_CKE1) U2(DDR_ODT1); U60 A3(NU)* A7(NF/TDQS#) F1(NU)* F9(NU)* H1(NU)* H9(NU)*; U61 5(NC)*; U64 5(NC)*; U75 1(NC)

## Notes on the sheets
sheet 11
- Key Pad - Top Side
- Status LED's
sheet 13
- ARM MPU AM437X General Purpose EVM
- -See the Hardware User Guide for board details
- -See the Errata document for the board for details
- -See the PCB Build Specification for PCB Details
sheet 14
- ID Memory
- JTAG Connector
- Boot Configuration
sheet 16
- USB0 Port
sheet 17
- USB1 Port
